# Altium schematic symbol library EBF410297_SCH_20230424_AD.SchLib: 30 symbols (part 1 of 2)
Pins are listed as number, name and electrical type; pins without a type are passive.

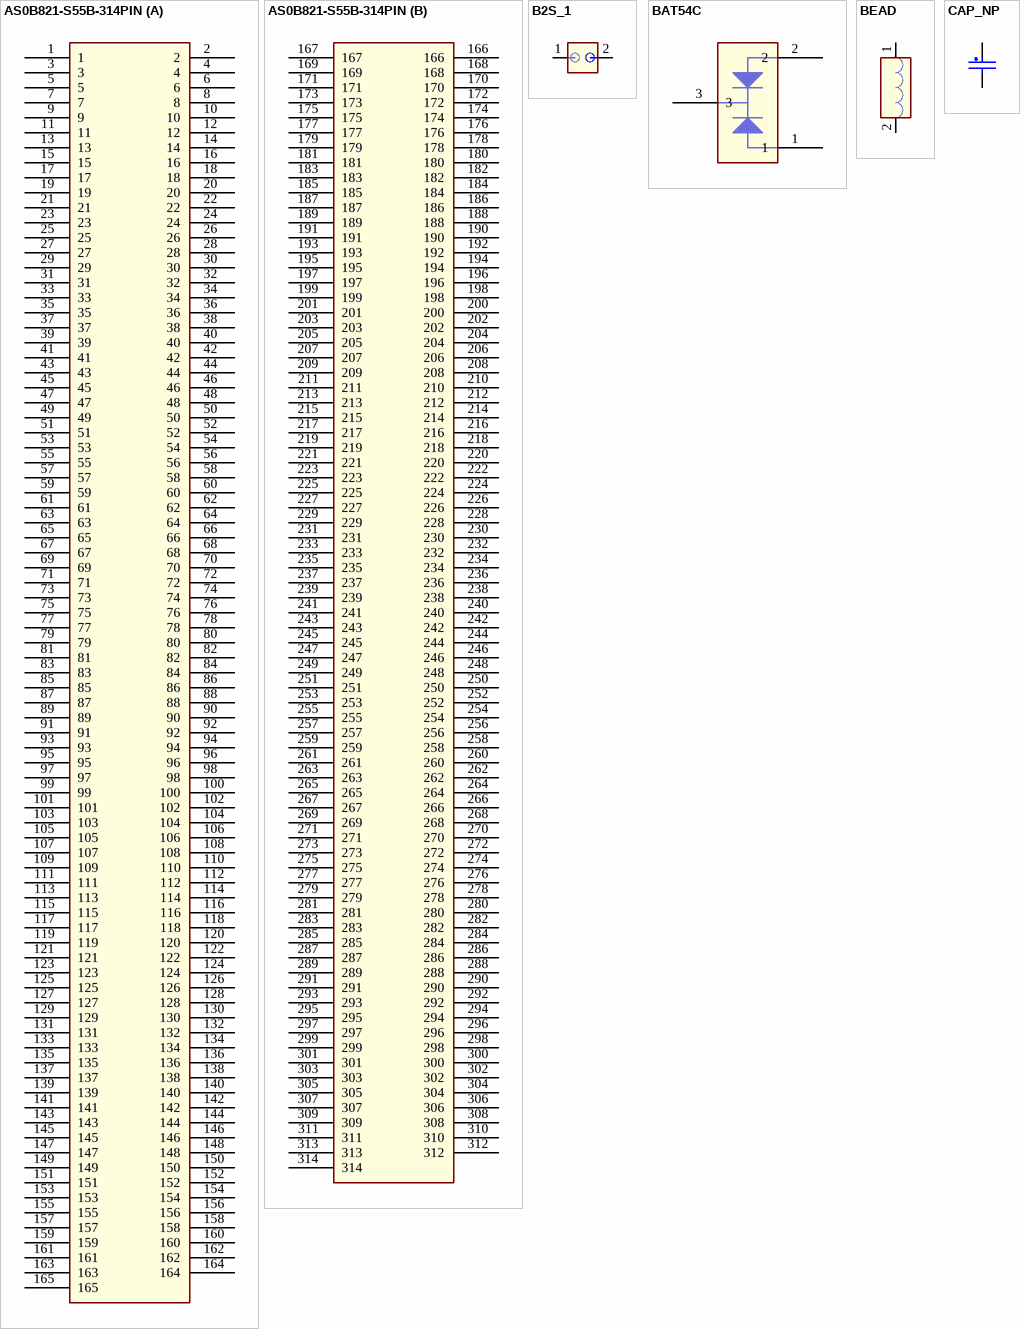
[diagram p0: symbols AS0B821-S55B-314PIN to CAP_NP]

## AS0B821-S55B-314PIN
designator J?
footprint AS0B821-S78B-314PIN
part A pins: 1, 2, 3, 4, 5, 6, 7, 8, 9, 10, 11, 12, 13, 14, 15, 16, 17, 18, 19, 20, 21, 22, 23, 24, 25, 26, 27, 28, 29, 30, 31, 32, 33, 34, 35, 36, 37, 38, 39, 40, 41, 42, 43, 44, 45, 46, 47, 48, 49, 50, 51, 52, 53, 54, 55, 56, 57, 58, 59, 60, 61, 62, 63, 64, 65, 66, 67, 68, 69, 70, 71, 72, 73, 74, 75, 76, 77, 78, 79, 80, 81, 82, 83, 84, 85, 86, 87, 88, 89, 90, 91, 92, 93, 94, 95, 96, 97, 98, 99, 100, 101, 102, 103, 104, 105, 106, 107, 108, 109, 110, 111, 112, 113, 114, 115, 116, 117, 118, 119, 120, 121, 122, 123, 124, 125, 126, 127, 128, 129, 130, 131, 132, 133, 134, 135, 136, 137, 138, 139, 140, 141, 142, 143, 144, 145, 146, 147, 148, 149, 150, 151, 152, 153, 154, 155, 156, 157, 158, 159, 160, 161, 162, 163, 164, 165
part B pins: 166, 167, 168, 169, 170, 171, 172, 173, 174, 175, 176, 177, 178, 179, 180, 181, 182, 183, 184, 185, 186, 187, 188, 189, 190, 191, 192, 193, 194, 195, 196, 197, 198, 199, 200, 201, 202, 203, 204, 205, 206, 207, 208, 209, 210, 211, 212, 213, 214, 215, 216, 217, 218, 219, 220, 221, 222, 223, 224, 225, 226, 227, 228, 229, 230, 231, 232, 233, 234, 235, 236, 237, 238, 239, 240, 241, 242, 243, 244, 245, 246, 247, 248, 249, 250, 251, 252, 253, 254, 255, 256, 257, 258, 259, 260, 261, 262, 263, 264, 265, 266, 267, 268, 269, 270, 271, 272, 273, 274, 275, 276, 277, 278, 279, 280, 281, 282, 283, 284, 285, 286, 287, 288, 289, 290, 291, 292, 293, 294, 295, 296, 297, 298, 299, 300, 301, 302, 303, 304, 305, 306, 307, 308, 309, 310, 311, 312, 313, 314

## B2S_1
designator J?
pins: 1, 2

## BAT54C
designator D?
footprint SOT23
pins: 1, 2, 3

## BEAD
designator L?
CLASS: DISCRETE
pins: 1, 2

## CAP_NP
designator C?
CLASS: DISCRETE
pins: 1, 2

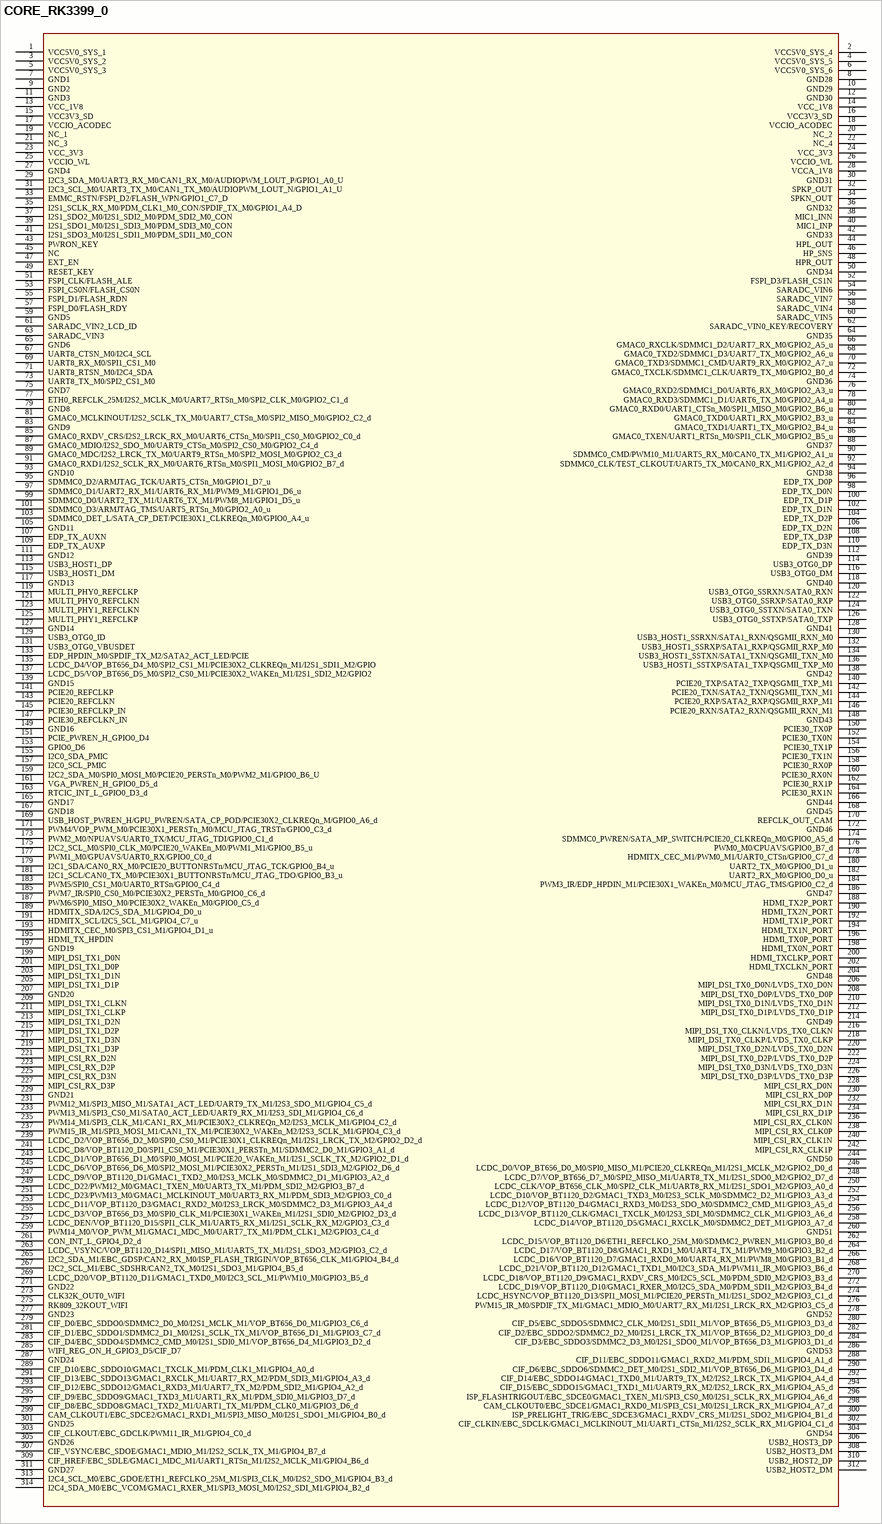
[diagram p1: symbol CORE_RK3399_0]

## CORE_RK3399_0
designator U?
pins: 1 VCC5V0_SYS_1, 2 VCC5V0_SYS_4, 3 VCC5V0_SYS_2, 4 VCC5V0_SYS_5, 5 VCC5V0_SYS_3, 6 VCC5V0_SYS_6, 7 GND1, 8 GND28, 9 GND2, 10 GND29, 11 GND3, 12 GND30, 13 VCC_1V8, 14 VCC_1V8, 15 VCC3V3_SD, 16 VCC3V3_SD, 17 VCCIO_ACODEC, 18 VCCIO_ACODEC, 19 NC_1, 20 NC_2, 21 NC_3, 22 NC_4, 23 VCC_3V3, 24 VCC_3V3, 25 VCCIO_WL, 26 VCCIO_WL, 27 GND4, 28 VCCA_1V8, 29 I2C3_SDA_M0/UART3_RX_M0/CAN1_RX_M0/AUDIOPWM_LOUT_P/GPIO1_A0_U, 30 GND31, 31 I2C3_SCL_M0/UART3_TX_M0/CAN1_TX_M0/AUDIOPWM_LOUT_N/GPIO1_A1_U, 32 SPKP_OUT, 33 EMMC_RSTN/FSPI_D2/FLASH_WPN/GPIO1_C7_D, 34 SPKN_OUT, 35 I2S1_SCLK_RX_M0/PDM_CLK1_M0_CON/SPDIF_TX_M0/GPIO1_A4_D, 36 GND32, 37 I2S1_SDO2_M0/I2S1_SDI2_M0/PDM_SDI2_M0_CON, 38 MIC1_INN, 39 I2S1_SDO1_M0/I2S1_SDI3_M0/PDM_SDI3_M0_CON, 40 MIC1_INP, 41 I2S1_SDO3_M0/I2S1_SDI1_M0/PDM_SDI1_M0_CON, 42 GND33, 43 PWRON_KEY, 44 HPL_OUT, 45 NC, 46 HP_SNS, 47 EXT_EN, 48 HPR_OUT, 49 RESET_KEY, 50 GND34, 51 FSPI_CLK/FLASH_ALE, 52 FSPI_D3/FLASH_CS1N, 53 FSPI_CS0N/FLASH_CS0N, 54 SARADC_VIN6, 55 FSPI_D1/FLASH_RDN, 56 SARADC_VIN7, 57 FSPI_D0/FLASH_RDY, 58 SARADC_VIN4, 59 GND5, 60 SARADC_VIN5, 61 SARADC_VIN2_LCD_ID, 62 SARADC_VIN0_KEY/RECOVERY, 63 SARADC_VIN3, 64 GND35, 65 GND6, 66 GMAC0_RXCLK/SDMMC1_D2/UART7_RX_M0/GPIO2_A5_u, 67 UART8_CTSN_M0/I2C4_SCL, 68 GMAC0_TXD2/SDMMC1_D3/UART7_TX_M0/GPIO2_A6_u, 69 UART8_RX_M0/SPI1_CS1_M0, 70 GMAC0_TXD3/SDMMC1_CMD/UART9_RX_M0/GPIO2_A7_u, 71 UART8_RTSN_M0/I2C4_SDA, 72 GMAC0_TXCLK/SDMMC1_CLK/UART9_TX_M0/GPIO2_B0_d, 73 UART8_TX_M0/SPI2_CS1_M0, 74 GND36, 75 GND7, 76 GMAC0_RXD2/SDMMC1_D0/UART6_RX_M0/GPIO2_A3_u, 77 ETH0_REFCLK_25M/I2S2_MCLK_M0/UART7_RTSn_M0/SPI2_CLK_M0/GPIO2_C1_d, 78 GMAC0_RXD3/SDMMC1_D1/UART6_TX_M0/GPIO2_A4_u, 79 GND8, 80 GMAC0_RXD0/UART1_CTSn_M0/SPI1_MISO_M0/GPIO2_B6_u, 81 GMAC0_MCLKINOUT/I2S2_SCLK_TX_M0/UART7_CTSn_M0/SPI2_MISO_M0/GPIO2_C2_d, 82 GMAC0_TXD0/UART1_RX_M0/GPIO2_B3_u, 83 GND9, 84 GMAC0_TXD1/UART1_TX_M0/GPIO2_B4_u, 85 GMAC0_RXDV_CRS/I2S2_LRCK_RX_M0/UART6_CTSn_M0/SPI1_CS0_M0/GPIO2_C0_d, 86 GMAC0_TXEN/UART1_RTSn_M0/SPI1_CLK_M0/GPIO2_B5_u, 87 GMAC0_MDIO/I2S2_SDO_M0/UART9_CTSn_M0/SPI2_CS0_M0/GPIO2_C4_d, 88 GND37, 89 GMAC0_MDC/I2S2_LRCK_TX_M0/UART9_RTSn_M0/SPI2_MOSI_M0/GPIO2_C3_d, 90 SDMMC0_CMD/PWM10_M1/UART5_RX_M0/CAN0_TX_M1/GPIO2_A1_u, 91 GMAC0_RXD1/I2S2_SCLK_RX_M0/UART6_RTSn_M0/SPI1_MOSI_M0/GPIO2_B7_d, 92 SDMMC0_CLK/TEST_CLKOUT/UART5_TX_M0/CAN0_RX_M1/GPIO2_A2_d, 93 GND10, 94 GND38, 95 SDMMC0_D2/ARMJTAG_TCK/UART5_CTSn_M0/GPIO1_D7_u, 96 EDP_TX_D0P, 97 SDMMC0_D1/UART2_RX_M1/UART6_RX_M1/PWM9_M1/GPIO1_D6_u, 98 EDP_TX_D0N, 99 SDMMC0_D0/UART2_TX_M1/UART6_TX_M1/PWM8_M1/GPIO1_D5_u, 100 EDP_TX_D1P, 101 SDMMC0_D3/ARMJTAG_TMS/UART5_RTSn_M0/GPIO2_A0_u, 102 EDP_TX_D1N, 103 SDMMC0_DET_L/SATA_CP_DET/PCIE30X1_CLKREQn_M0/GPIO0_A4_u, 104 EDP_TX_D2P, 105 GND11, 106 EDP_TX_D2N, 107 EDP_TX_AUXN, 108 EDP_TX_D3P, 109 EDP_TX_AUXP, 110 EDP_TX_D3N, 111 GND12, 112 GND39, 113 USB3_HOST1_DP, 114 USB3_OTG0_DP, 115 USB3_HOST1_DM, 116 USB3_OTG0_DM, 117 GND13, 118 GND40, 119 MULTI_PHY0_REFCLKP, 120 USB3_OTG0_SSRXN/SATA0_RXN, 121 MULTI_PHY0_REFCLKN, 122 USB3_OTG0_SSRXP/SATA0_RXP, 123 MULTI_PHY1_REFCLKN, 124 USB3_OTG0_SSTXN/SATA0_TXN, 125 MULTI_PHY1_REFCLKP, 126 USB3_OTG0_SSTXP/SATA0_TXP, 127 GND14, 128 GND41, 129 USB3_OTG0_ID, 130 USB3_HOST1_SSRXN/SATA1_RXN/QSGMII_RXN_M0, 131 USB3_OTG0_VBUSDET, 132 USB3_HOST1_SSRXP/SATA1_RXP/QSGMII_RXP_M0, 133 EDP_HPDIN_M0/SPDIF_TX_M2/SATA2_ACT_LED/PCIE, 134 USB3_HOST1_SSTXN/SATA1_TXN/QSGMII_TXN_M0, 135 LCDC_D4/VOP_BT656_D4_M0/SPI2_CS1_M1/PCIE30X2_CLKREQn_M1/I2S1_SDI1_M2/GPIO, 136 USB3_HOST1_SSTXP/SATA1_TXP/QSGMII_TXP_M0, 137 LCDC_D5/VOP_BT656_D5_M0/SPI2_CS0_M1/PCIE30X2_WAKEn_M1/I2S1_SDI2_M2/GPIO2, 138 GND42, 139 GND15, 140 PCIE20_TXP/SATA2_TXP/QSGMII_TXP_M1, 141 PCIE20_REFCLKP, 142 PCIE20_TXN/SATA2_TXN/QSGMII_TXN_M1, 143 PCIE20_REFCLKN, 144 PCIE20_RXP/SATA2_RXP/QSGMII_RXP_M1, 145 PCIE30_REFCLKP_IN, 146 PCIE20_RXN/SATA2_RXN/QSGMII_RXN_M1, 147 PCIE30_REFCLKN_IN, 148 GND43, 149 GND16, 150 PCIE30_TX0P, 151 PCIE_PWREN_H_GPIO0_D4, 152 PCIE30_TX0N, 153 GPIO0_D6, 154 PCIE30_TX1P, 155 I2C0_SDA_PMIC, 156 PCIE30_TX1N, 157 I2C0_SCL_PMIC, 158 PCIE30_RX0P, 159 I2C2_SDA_M0/SPI0_MOSI_M0/PCIE20_PERSTn_M0/PWM2_M1/GPIO0_B6_U, 160 PCIE30_RX0N, 161 VGA_PWREN_H_GPIO0_D5_d, 162 PCIE30_RX1P, 163 RTCIC_INT_L_GPIO0_D3_d, 164 PCIE30_RX1N, 165 GND17, 166 GND44, 167 GND18, 168 GND45, 169 USB_HOST_PWREN_H/GPU_PWREN/SATA_CP_POD/PCIE30X2_CLKREQn_M/GPIO0_A6_d, 170 REFCLK_OUT_CAM, 171 PWM4/VOP_PWM_M0/PCIE30X1_PERSTn_M0/MCU_JTAG_TRSTn/GPIO0_C3_d, 172 GND46, 173 PWM2_M0/NPUAVS/UART0_TX/MCU_JTAG_TDI/GPIO0_C1_d, 174 SDMMC0_PWREN/SATA_MP_SWITCH/PCIE20_CLKREQn_M0/GPIO0_A5_d, 175 I2C2_SCL_M0/SPI0_CLK_M0/PCIE20_WAKEn_M0/PWM1_M1/GPIO0_B5_u, 176 PWM0_M0/CPUAVS/GPIO0_B7_d, 177 PWM1_M0/GPUAVS/UART0_RX/GPIO0_C0_d, 178 HDMITX_CEC_M1/PWM0_M1/UART0_CTSn/GPIO0_C7_d, 179 I2C1_SDA/CAN0_RX_M0/PCIE20_BUTTONRSTn/MCU_JTAG_TCK/GPIO0_B4_u, 180 UART2_TX_M0/GPIO0_D1_u, 181 I2C1_SCL/CAN0_TX_M0/PCIE30X1_BUTTONRSTn/MCU_JTAG_TDO/GPIO0_B3_u, 182 UART2_RX_M0/GPIO0_D0_u, 183 PWM5/SPI0_CS1_M0/UART0_RTSn/GPIO0_C4_d, 184 PWM3_IR/EDP_HPDIN_M1/PCIE30X1_WAKEn_M0/MCU_JTAG_TMS/GPIO0_C2_d, 185 PWM7_IR/SPI0_CS0_M0/PCIE30X2_PERSTn_M0/GPIO0_C6_d, 186 GND47, 187 PWM6/SPI0_MISO_M0/PCIE30X2_WAKEn_M0/GPIO0_C5_d, 188 HDMI_TX2P_PORT, 189 HDMITX_SDA/I2C5_SDA_M1/GPIO4_D0_u, 190 HDMI_TX2N_PORT, 191 HDMITX_SCL/I2C5_SCL_M1/GPIO4_C7_u, 192 HDMI_TX1P_PORT, 193 HDMITX_CEC_M0/SPI3_CS1_M1/GPIO4_D1_u, 194 HDMI_TX1N_PORT, 195 HDMI_TX_HPDIN, 196 HDMI_TX0P_PORT, 197 GND19, 198 HDMI_TX0N_PORT, 199 MIPI_DSI_TX1_D0N, 200 HDMI_TXCLKP_PORT, 201 MIPI_DSI_TX1_D0P, 202 HDMI_TXCLKN_PORT, 203 MIPI_DSI_TX1_D1N, 204 GND48, 205 MIPI_DSI_TX1_D1P, 206 MIPI_DSI_TX0_D0N/LVDS_TX0_D0N, 207 GND20, 208 MIPI_DSI_TX0_D0P/LVDS_TX0_D0P, 209 MIPI_DSI_TX1_CLKN, 210 MIPI_DSI_TX0_D1N/LVDS_TX0_D1N, 211 MIPI_DSI_TX1_CLKP, 212 MIPI_DSI_TX0_D1P/LVDS_TX0_D1P, 213 MIPI_DSI_TX1_D2N, 214 GND49, 215 MIPI_DSI_TX1_D2P, 216 MIPI_DSI_TX0_CLKN/LVDS_TX0_CLKN, 217 MIPI_DSI_TX1_D3N, 218 MIPI_DSI_TX0_CLKP/LVDS_TX0_CLKP, 219 MIPI_DSI_TX1_D3P, 220 MIPI_DSI_TX0_D2N/LVDS_TX0_D2N, 221 MIPI_CSI_RX_D2N, 222 MIPI_DSI_TX0_D2P/LVDS_TX0_D2P, 223 MIPI_CSI_RX_D2P, 224 MIPI_DSI_TX0_D3N/LVDS_TX0_D3N, 225 MIPI_CSI_RX_D3N, 226 MIPI_DSI_TX0_D3P/LVDS_TX0_D3P, 227 MIPI_CSI_RX_D3P, 228 MIPI_CSI_RX_D0N, 229 GND21, 230 MIPI_CSI_RX_D0P, 231 PWM12_M1/SPI3_MISO_M1/SATA1_ACT_LED/UART9_TX_M1/I2S3_SDO_M1/GPIO4_C5_d, 232 MIPI_CSI_RX_D1N, 233 PWM13_M1/SPI3_CS0_M1/SATA0_ACT_LED/UART9_RX_M1/I2S3_SDI_M1/GPIO4_C6_d, 234 MIPI_CSI_RX_D1P, 235 PWM14_M1/SPI3_CLK_M1/CAN1_RX_M1/PCIE30X2_CLKREQn_M2/I2S3_MCLK_M1/GPIO4_C2_d, 236 MIPI_CSI_RX_CLK0N, 237 PWM15_IR_M1/SPI3_MOSI_M1/CAN1_TX_M1/PCIE30X2_WAKEn_M2/I2S3_SCLK_M1/GPIO4_C3_d, 238 MIPI_CSI_RX_CLK0P, 239 LCDC_D2/VOP_BT656_D2_M0/SPI0_CS0_M1/PCIE30X1_CLKREQn_M1/I2S1_LRCK_TX_M2/GPIO2_D2_d, 240 MIPI_CSI_RX_CLK1N, 241 LCDC_D8/VOP_BT1120_D0/SPI1_CS0_M1/PCIE30X1_PERSTn_M1/SDMMC2_D0_M1/GPIO3_A1_d, 242 MIPI_CSI_RX_CLK1P, 243 LCDC_D1/VOP_BT656_D1_M0/SPI0_MOSI_M1/PCIE20_WAKEn_M1/I2S1_SCLK_TX_M2/GPIO2_D1_d, 244 GND50, 245 LCDC_D6/VOP_BT656_D6_M0/SPI2_MOSI_M1/PCIE30X2_PERSTn_M1/I2S1_SDI3_M2/GPIO2_D6_d, 246 LCDC_D0/VOP_BT656_D0_M0/SPI0_MISO_M1/PCIE20_CLKREQn_M1/I2S1_MCLK_M2/GPIO2_D0_d, 247 LCDC_D9/VOP_BT1120_D1/GMAC1_TXD2_M0/I2S3_MCLK_M0/SDMMC2_D1_M1/GPIO3_A2_d, 248 LCDC_D7/VOP_BT656_D7_M0/SPI2_MISO_M1/UART8_TX_M1/I2S1_SDO0_M2/GPIO2_D7_d, 249 LCDC_D22/PWM12_M0/GMAC1_TXEN_M0/UART3_TX_M1/PDM_SDI2_M2/GPIO3_B7_d, 250 LCDC_CLK/VOP_BT656_CLK_M0/SPI2_CLK_M1/UART8_RX_M1/I2S1_SDO1_M2/GPIO3_A0_d, 251 LCDC_D23/PWM13_M0/GMAC1_MCLKINOUT_M0/UART3_RX_M1/PDM_SDI3_M2/GPIO3_C0_d, 252 LCDC_D10/VOP_BT1120_D2/GMAC1_TXD3_M0/I2S3_SCLK_M0/SDMMC2_D2_M1/GPIO3_A3_d, 253 LCDC_D11/VOP_BT1120_D3/GMAC1_RXD2_M0/I2S3_LRCK_M0/SDMMC2_D3_M1/GPIO3_A4_d, 254 LCDC_D12/VOP_BT1120_D4/GMAC1_RXD3_M0/I2S3_SDO_M0/SDMMC2_CMD_M1/GPIO3_A5_d, 255 LCDC_D3/VOP_BT656_D3_M0/SPI0_CLK_M1/PCIE30X1_WAKEn_M1/I2S1_SDI0_M2/GPIO2_D3_d, 256 LCDC_D13/VOP_BT1120_CLK/GMAC1_TXCLK_M0/I2S3_SDI_M0/SDMMC2_CLK_M1/GPIO3_A6_d, 257 LCDC_DEN/VOP_BT1120_D15/SPI1_CLK_M1/UART5_RX_M1/I2S1_SCLK_RX_M2/GPIO3_C3_d, 258 LCDC_D14/VOP_BT1120_D5/GMAC1_RXCLK_M0/SDMMC2_DET_M1/GPIO3_A7_d, 259 PWM14_M0/VOP_PWM_M1/GMAC1_MDC_M0/UART7_TX_M1/PDM_CLK1_M2/GPIO3_C4_d, 260 GND51, 261 CON_INT_L_GPIO4_D2_d, 262 LCDC_D15/VOP_BT1120_D6/ETH1_REFCLKO_25M_M0/SDMMC2_PWREN_M1/GPIO3_B0_d, 263 LCDC_VSYNC/VOP_BT1120_D14/SPI1_MISO_M1/UART5_TX_M1/I2S1_SDO3_M2/GPIO3_C2_d, 264 LCDC_D17/VOP_BT1120_D8/GMAC1_RXD1_M0/UART4_TX_M1/PWM9_M0/GPIO3_B2_d, 265 I2C2_SDA_M1/EBC_GDSP/CAN2_RX_M0/ISP_FLASH_TRIGIN/VOP_BT656_CLK_M1/GPIO4_B4_d, 266 LCDC_D16/VOP_BT1120_D7/GMAC1_RXD0_M0/UART4_RX_M1/PWM8_M0/GPIO3_B1_d, 267 I2C2_SCL_M1/EBC_SDSHR/CAN2_TX_M0/I2S1_SDO3_M1/GPIO4_B5_d, 268 LCDC_D21/VOP_BT1120_D12/GMAC1_TXD1_M0/I2C3_SDA_M1/PWM11_IR_M0/GPIO3_B6_d, 269 LCDC_D20/VOP_BT1120_D11/GMAC1_TXD0_M0/I2C3_SCL_M1/PWM10_M0/GPIO3_B5_d, 270 LCDC_D18/VOP_BT1120_D9/GMAC1_RXDV_CRS_M0/I2C5_SCL_M0/PDM_SDI0_M2/GPIO3_B3_d, 271 GND22, 272 LCDC_D19/VOP_BT1120_D10/GMAC1_RXER_M0/I2C5_SDA_M0/PDM_SDI1_M2/GPIO3_B4_d, 273 CLK32K_OUT0_WIFI, 274 LCDC_HSYNC/VOP_BT1120_D13/SPI1_MOSI_M1/PCIE20_PERSTn_M1/I2S1_SDO2_M2/GPIO3_C1_d, 275 RK809_32KOUT_WIFI, 276 PWM15_IR_M0/SPDIF_TX_M1/GMAC1_MDIO_M0/UART7_RX_M1/I2S1_LRCK_RX_M2/GPIO3_C5_d, 277 GND23, 278 GND52, 279 CIF_D0/EBC_SDDO0/SDMMC2_D0_M0/I2S1_MCLK_M1/VOP_BT656_D0_M1/GPIO3_C6_d, 280 CIF_D5/EBC_SDDO5/SDMMC2_CLK_M0/I2S1_SDI1_M1/VOP_BT656_D5_M1/GPIO3_D3_d, 281 CIF_D1/EBC_SDDO1/SDMMC2_D1_M0/I2S1_SCLK_TX_M1/VOP_BT656_D1_M1/GPIO3_C7_d, 282 CIF_D2/EBC_SDDO2/SDMMC2_D2_M0/I2S1_LRCK_TX_M1/VOP_BT656_D2_M1/GPIO3_D0_d, 283 CIF_D4/EBC_SDDO4/SDMMC2_CMD_M0/I2S1_SDI0_M1/VOP_BT656_D4_M1/GPIO3_D2_d, 284 CIF_D3/EBC_SDDO3/SDMMC2_D3_M0/I2S1_SDO0_M1/VOP_BT656_D3_M1/GPIO3_D1_d, 285 WIFI_REG_ON_H_GPIO3_D5/CIF_D7, 286 GND53, 287 GND24, 288 CIF_D11/EBC_SDDO11/GMAC1_RXD2_M1/PDM_SDI1_M1/GPIO4_A1_d, 289 CIF_D10/EBC_SDDO10/GMAC1_TXCLK_M1/PDM_CLK1_M1/GPIO4_A0_d, 290 CIF_D6/EBC_SDDO6/SDMMC2_DET_M0/I2S1_SDI2_M1/VOP_BT656_D6_M1/GPIO3_D4_d, 291 CIF_D13/EBC_SDDO13/GMAC1_RXCLK_M1/UART7_RX_M2/PDM_SDI3_M1/GPIO4_A3_d, 292 CIF_D14/EBC_SDDO14/GMAC1_TXD0_M1/UART9_TX_M2/I2S2_LRCK_TX_M1/GPIO4_A4_d, 293 CIF_D12/EBC_SDDO12/GMAC1_RXD3_M1/UART7_TX_M2/PDM_SDI2_M1/GPIO4_A2_d, 294 CIF_D15/EBC_SDDO15/GMAC1_TXD1_M1/UART9_RX_M2/I2S2_LRCK_RX_M1/GPIO4_A5_d, 295 CIF_D9/EBC_SDDO9/GMAC1_TXD3_M1/UART1_RX_M1/PDM_SDI0_M1/GPIO3_D7_d, 296 ISP_FLASHTRIGOUT/EBC_SDCE0/GMAC1_TXEN_M1/SPI3_CS0_M0/I2S1_SCLK_RX_M1/GPIO4_A6_d, 297 CIF_D8/EBC_SDDO8/GMAC1_TXD2_M1/UART1_TX_M1/PDM_CLK0_M1/GPIO3_D6_d, 298 CAM_CLKOUT0/EBC_SDCE1/GMAC1_RXD0_M1/SPI3_CS1_M0/I2S1_LRCK_RX_M1/GPIO4_A7_d, 299 CAM_CLKOUT1/EBC_SDCE2/GMAC1_RXD1_M1/SPI3_MISO_M0/I2S1_SDO1_M1/GPIO4_B0_d, 300 ISP_PRELIGHT_TRIG/EBC_SDCE3/GMAC1_RXDV_CRS_M1/I2S1_SDO2_M1/GPIO4_B1_d, 301 GND25, 302 CIF_CLKIN/EBC_SDCLK/GMAC1_MCLKINOUT_M1/UART1_CTSn_M1/I2S2_SCLK_RX_M1/GPIO4_C1_d, 303 CIF_CLKOUT/EBC_GDCLK/PWM11_IR_M1/GPIO4_C0_d, 304 GND54, 305 GND26, 306 USB2_HOST3_DP, 307 CIF_VSYNC/EBC_SDOE/GMAC1_MDIO_M1/I2S2_SCLK_TX_M1/GPIO4_B7_d, 308 USB2_HOST3_DM, 309 CIF_HREF/EBC_SDLE/GMAC1_MDC_M1/UART1_RTSn_M1/I2S2_MCLK_M1/GPIO4_B6_d, 310 USB2_HOST2_DP, 311 GND27, 312 USB2_HOST2_DM, 313 I2C4_SCL_M0/EBC_GDOE/ETH1_REFCLKO_25M_M1/SPI3_CLK_M0/I2S2_SDO_M1/GPIO4_B3_d, 314 I2C4_SDA_M0/EBC_VCOM/GMAC1_RXER_M1/SPI3_MOSI_M0/I2S2_SDI_M1/GPIO4_B2_d

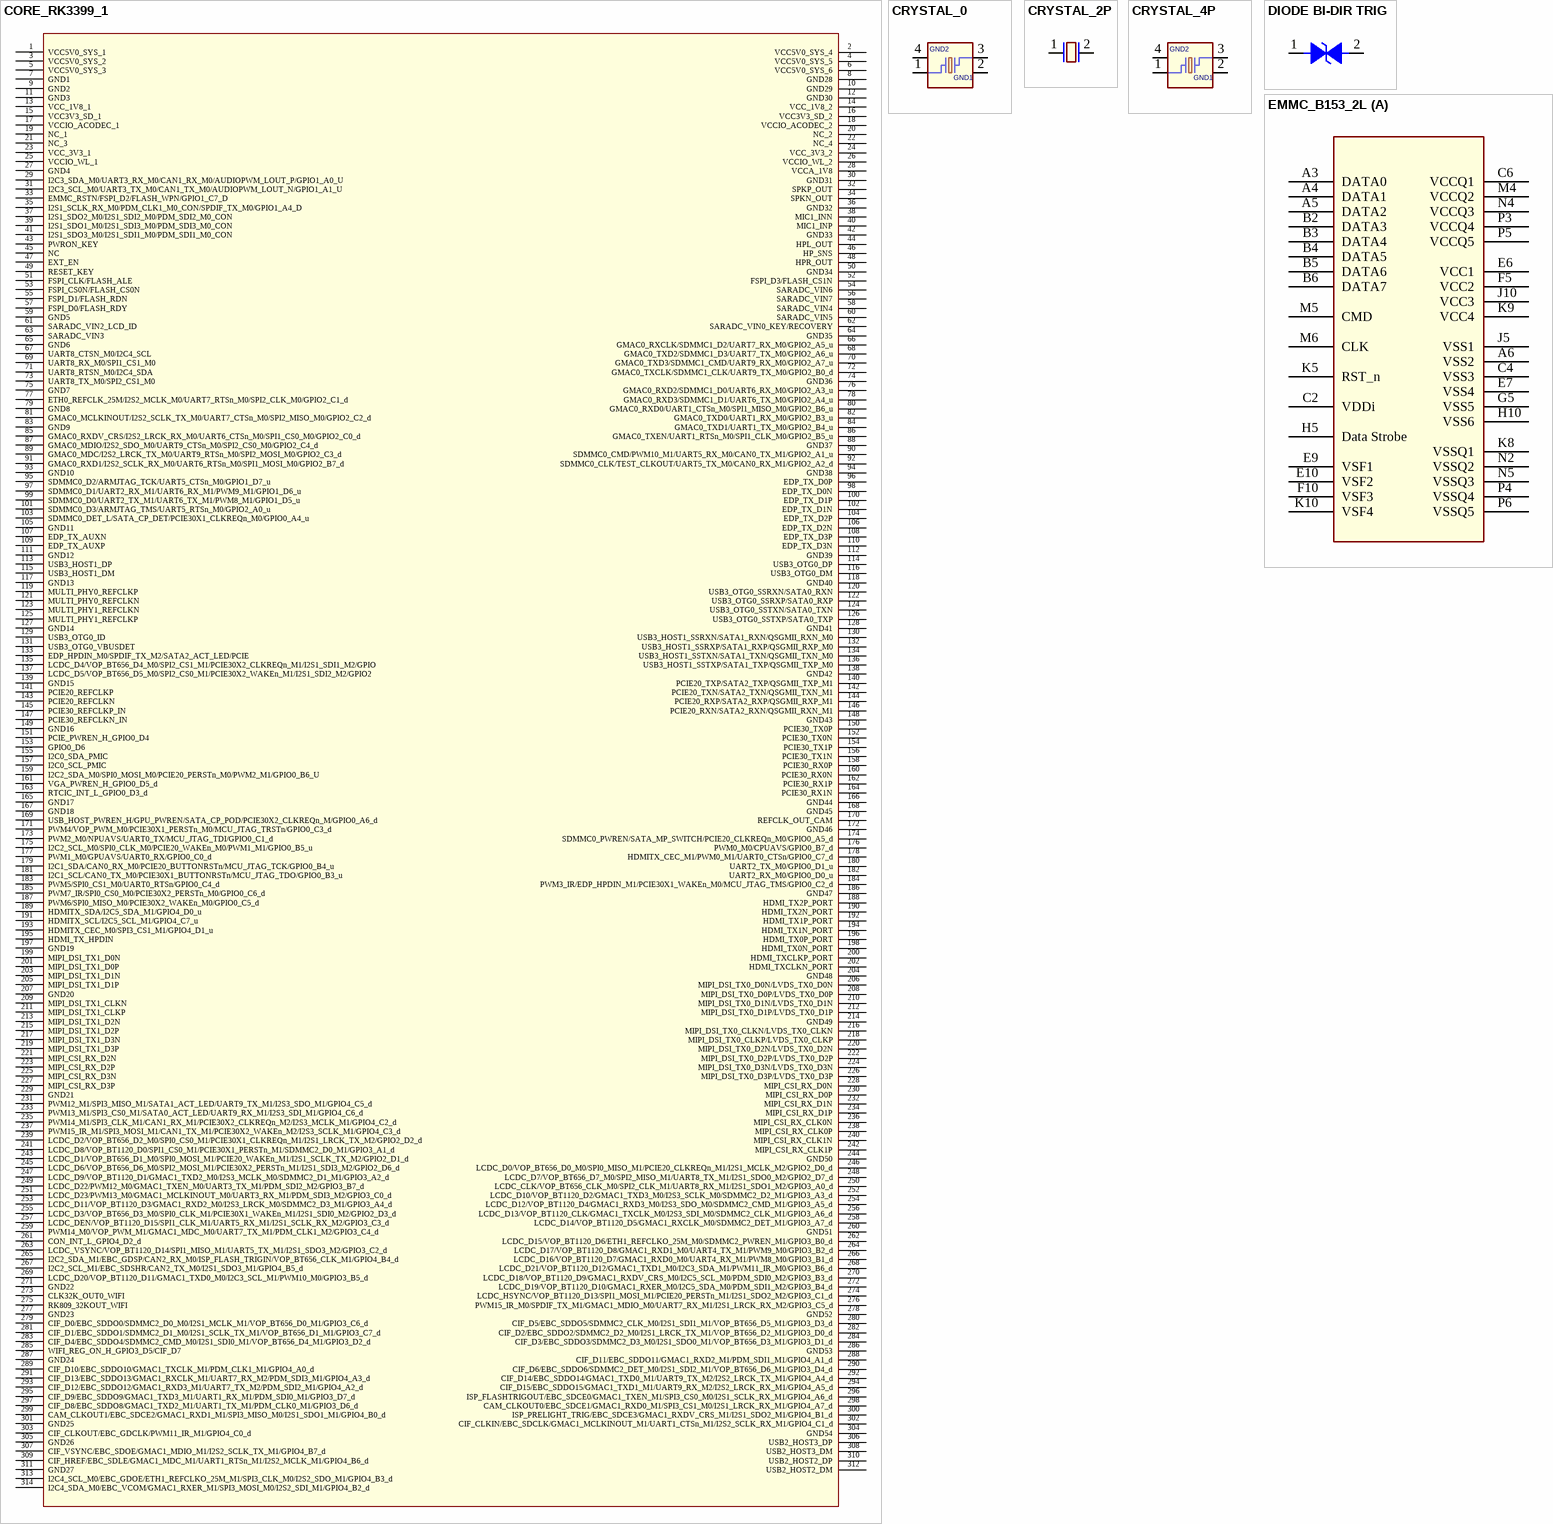
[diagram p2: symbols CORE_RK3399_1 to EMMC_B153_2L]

## CORE_RK3399_1
designator U?
pins: 1 VCC5V0_SYS_1, 2 VCC5V0_SYS_4, 3 VCC5V0_SYS_2, 4 VCC5V0_SYS_5, 5 VCC5V0_SYS_3, 6 VCC5V0_SYS_6, 7 GND1, 8 GND28, 9 GND2, 10 GND29, 11 GND3, 12 GND30, 13 VCC_1V8_1, 14 VCC_1V8_2, 15 VCC3V3_SD_1, 16 VCC3V3_SD_2, 17 VCCIO_ACODEC_1, 18 VCCIO_ACODEC_2, 19 NC_1, 20 NC_2, 21 NC_3, 22 NC_4, 23 VCC_3V3_1, 24 VCC_3V3_2, 25 VCCIO_WL_1, 26 VCCIO_WL_2, 27 GND4, 28 VCCA_1V8, 29 I2C3_SDA_M0/UART3_RX_M0/CAN1_RX_M0/AUDIOPWM_LOUT_P/GPIO1_A0_U, 30 GND31, 31 I2C3_SCL_M0/UART3_TX_M0/CAN1_TX_M0/AUDIOPWM_LOUT_N/GPIO1_A1_U, 32 SPKP_OUT, 33 EMMC_RSTN/FSPI_D2/FLASH_WPN/GPIO1_C7_D, 34 SPKN_OUT, 35 I2S1_SCLK_RX_M0/PDM_CLK1_M0_CON/SPDIF_TX_M0/GPIO1_A4_D, 36 GND32, 37 I2S1_SDO2_M0/I2S1_SDI2_M0/PDM_SDI2_M0_CON, 38 MIC1_INN, 39 I2S1_SDO1_M0/I2S1_SDI3_M0/PDM_SDI3_M0_CON, 40 MIC1_INP, 41 I2S1_SDO3_M0/I2S1_SDI1_M0/PDM_SDI1_M0_CON, 42 GND33, 43 PWRON_KEY, 44 HPL_OUT, 45 NC, 46 HP_SNS, 47 EXT_EN, 48 HPR_OUT, 49 RESET_KEY, 50 GND34, 51 FSPI_CLK/FLASH_ALE, 52 FSPI_D3/FLASH_CS1N, 53 FSPI_CS0N/FLASH_CS0N, 54 SARADC_VIN6, 55 FSPI_D1/FLASH_RDN, 56 SARADC_VIN7, 57 FSPI_D0/FLASH_RDY, 58 SARADC_VIN4, 59 GND5, 60 SARADC_VIN5, 61 SARADC_VIN2_LCD_ID, 62 SARADC_VIN0_KEY/RECOVERY, 63 SARADC_VIN3, 64 GND35, 65 GND6, 66 GMAC0_RXCLK/SDMMC1_D2/UART7_RX_M0/GPIO2_A5_u, 67 UART8_CTSN_M0/I2C4_SCL, 68 GMAC0_TXD2/SDMMC1_D3/UART7_TX_M0/GPIO2_A6_u, 69 UART8_RX_M0/SPI1_CS1_M0, 70 GMAC0_TXD3/SDMMC1_CMD/UART9_RX_M0/GPIO2_A7_u, 71 UART8_RTSN_M0/I2C4_SDA, 72 GMAC0_TXCLK/SDMMC1_CLK/UART9_TX_M0/GPIO2_B0_d, 73 UART8_TX_M0/SPI2_CS1_M0, 74 GND36, 75 GND7, 76 GMAC0_RXD2/SDMMC1_D0/UART6_RX_M0/GPIO2_A3_u, 77 ETH0_REFCLK_25M/I2S2_MCLK_M0/UART7_RTSn_M0/SPI2_CLK_M0/GPIO2_C1_d, 78 GMAC0_RXD3/SDMMC1_D1/UART6_TX_M0/GPIO2_A4_u, 79 GND8, 80 GMAC0_RXD0/UART1_CTSn_M0/SPI1_MISO_M0/GPIO2_B6_u, 81 GMAC0_MCLKINOUT/I2S2_SCLK_TX_M0/UART7_CTSn_M0/SPI2_MISO_M0/GPIO2_C2_d, 82 GMAC0_TXD0/UART1_RX_M0/GPIO2_B3_u, 83 GND9, 84 GMAC0_TXD1/UART1_TX_M0/GPIO2_B4_u, 85 GMAC0_RXDV_CRS/I2S2_LRCK_RX_M0/UART6_CTSn_M0/SPI1_CS0_M0/GPIO2_C0_d, 86 GMAC0_TXEN/UART1_RTSn_M0/SPI1_CLK_M0/GPIO2_B5_u, 87 GMAC0_MDIO/I2S2_SDO_M0/UART9_CTSn_M0/SPI2_CS0_M0/GPIO2_C4_d, 88 GND37, 89 GMAC0_MDC/I2S2_LRCK_TX_M0/UART9_RTSn_M0/SPI2_MOSI_M0/GPIO2_C3_d, 90 SDMMC0_CMD/PWM10_M1/UART5_RX_M0/CAN0_TX_M1/GPIO2_A1_u, 91 GMAC0_RXD1/I2S2_SCLK_RX_M0/UART6_RTSn_M0/SPI1_MOSI_M0/GPIO2_B7_d, 92 SDMMC0_CLK/TEST_CLKOUT/UART5_TX_M0/CAN0_RX_M1/GPIO2_A2_d, 93 GND10, 94 GND38, 95 SDMMC0_D2/ARMJTAG_TCK/UART5_CTSn_M0/GPIO1_D7_u, 96 EDP_TX_D0P, 97 SDMMC0_D1/UART2_RX_M1/UART6_RX_M1/PWM9_M1/GPIO1_D6_u, 98 EDP_TX_D0N, 99 SDMMC0_D0/UART2_TX_M1/UART6_TX_M1/PWM8_M1/GPIO1_D5_u, 100 EDP_TX_D1P, 101 SDMMC0_D3/ARMJTAG_TMS/UART5_RTSn_M0/GPIO2_A0_u, 102 EDP_TX_D1N, 103 SDMMC0_DET_L/SATA_CP_DET/PCIE30X1_CLKREQn_M0/GPIO0_A4_u, 104 EDP_TX_D2P, 105 GND11, 106 EDP_TX_D2N, 107 EDP_TX_AUXN, 108 EDP_TX_D3P, 109 EDP_TX_AUXP, 110 EDP_TX_D3N, 111 GND12, 112 GND39, 113 USB3_HOST1_DP, 114 USB3_OTG0_DP, 115 USB3_HOST1_DM, 116 USB3_OTG0_DM, 117 GND13, 118 GND40, 119 MULTI_PHY0_REFCLKP, 120 USB3_OTG0_SSRXN/SATA0_RXN, 121 MULTI_PHY0_REFCLKN, 122 USB3_OTG0_SSRXP/SATA0_RXP, 123 MULTI_PHY1_REFCLKN, 124 USB3_OTG0_SSTXN/SATA0_TXN, 125 MULTI_PHY1_REFCLKP, 126 USB3_OTG0_SSTXP/SATA0_TXP, 127 GND14, 128 GND41, 129 USB3_OTG0_ID, 130 USB3_HOST1_SSRXN/SATA1_RXN/QSGMII_RXN_M0, 131 USB3_OTG0_VBUSDET, 132 USB3_HOST1_SSRXP/SATA1_RXP/QSGMII_RXP_M0, 133 EDP_HPDIN_M0/SPDIF_TX_M2/SATA2_ACT_LED/PCIE, 134 USB3_HOST1_SSTXN/SATA1_TXN/QSGMII_TXN_M0, 135 LCDC_D4/VOP_BT656_D4_M0/SPI2_CS1_M1/PCIE30X2_CLKREQn_M1/I2S1_SDI1_M2/GPIO, 136 USB3_HOST1_SSTXP/SATA1_TXP/QSGMII_TXP_M0, 137 LCDC_D5/VOP_BT656_D5_M0/SPI2_CS0_M1/PCIE30X2_WAKEn_M1/I2S1_SDI2_M2/GPIO2, 138 GND42, 139 GND15, 140 PCIE20_TXP/SATA2_TXP/QSGMII_TXP_M1, 141 PCIE20_REFCLKP, 142 PCIE20_TXN/SATA2_TXN/QSGMII_TXN_M1, 143 PCIE20_REFCLKN, 144 PCIE20_RXP/SATA2_RXP/QSGMII_RXP_M1, 145 PCIE30_REFCLKP_IN, 146 PCIE20_RXN/SATA2_RXN/QSGMII_RXN_M1, 147 PCIE30_REFCLKN_IN, 148 GND43, 149 GND16, 150 PCIE30_TX0P, 151 PCIE_PWREN_H_GPIO0_D4, 152 PCIE30_TX0N, 153 GPIO0_D6, 154 PCIE30_TX1P, 155 I2C0_SDA_PMIC, 156 PCIE30_TX1N, 157 I2C0_SCL_PMIC, 158 PCIE30_RX0P, 159 I2C2_SDA_M0/SPI0_MOSI_M0/PCIE20_PERSTn_M0/PWM2_M1/GPIO0_B6_U, 160 PCIE30_RX0N, 161 VGA_PWREN_H_GPIO0_D5_d, 162 PCIE30_RX1P, 163 RTCIC_INT_L_GPIO0_D3_d, 164 PCIE30_RX1N, 165 GND17, 166 GND44, 167 GND18, 168 GND45, 169 USB_HOST_PWREN_H/GPU_PWREN/SATA_CP_POD/PCIE30X2_CLKREQn_M/GPIO0_A6_d, 170 REFCLK_OUT_CAM, 171 PWM4/VOP_PWM_M0/PCIE30X1_PERSTn_M0/MCU_JTAG_TRSTn/GPIO0_C3_d, 172 GND46, 173 PWM2_M0/NPUAVS/UART0_TX/MCU_JTAG_TDI/GPIO0_C1_d, 174 SDMMC0_PWREN/SATA_MP_SWITCH/PCIE20_CLKREQn_M0/GPIO0_A5_d, 175 I2C2_SCL_M0/SPI0_CLK_M0/PCIE20_WAKEn_M0/PWM1_M1/GPIO0_B5_u, 176 PWM0_M0/CPUAVS/GPIO0_B7_d, 177 PWM1_M0/GPUAVS/UART0_RX/GPIO0_C0_d, 178 HDMITX_CEC_M1/PWM0_M1/UART0_CTSn/GPIO0_C7_d, 179 I2C1_SDA/CAN0_RX_M0/PCIE20_BUTTONRSTn/MCU_JTAG_TCK/GPIO0_B4_u, 180 UART2_TX_M0/GPIO0_D1_u, 181 I2C1_SCL/CAN0_TX_M0/PCIE30X1_BUTTONRSTn/MCU_JTAG_TDO/GPIO0_B3_u, 182 UART2_RX_M0/GPIO0_D0_u, 183 PWM5/SPI0_CS1_M0/UART0_RTSn/GPIO0_C4_d, 184 PWM3_IR/EDP_HPDIN_M1/PCIE30X1_WAKEn_M0/MCU_JTAG_TMS/GPIO0_C2_d, 185 PWM7_IR/SPI0_CS0_M0/PCIE30X2_PERSTn_M0/GPIO0_C6_d, 186 GND47, 187 PWM6/SPI0_MISO_M0/PCIE30X2_WAKEn_M0/GPIO0_C5_d, 188 HDMI_TX2P_PORT, 189 HDMITX_SDA/I2C5_SDA_M1/GPIO4_D0_u, 190 HDMI_TX2N_PORT, 191 HDMITX_SCL/I2C5_SCL_M1/GPIO4_C7_u, 192 HDMI_TX1P_PORT, 193 HDMITX_CEC_M0/SPI3_CS1_M1/GPIO4_D1_u, 194 HDMI_TX1N_PORT, 195 HDMI_TX_HPDIN, 196 HDMI_TX0P_PORT, 197 GND19, 198 HDMI_TX0N_PORT, 199 MIPI_DSI_TX1_D0N, 200 HDMI_TXCLKP_PORT, 201 MIPI_DSI_TX1_D0P, 202 HDMI_TXCLKN_PORT, 203 MIPI_DSI_TX1_D1N, 204 GND48, 205 MIPI_DSI_TX1_D1P, 206 MIPI_DSI_TX0_D0N/LVDS_TX0_D0N, 207 GND20, 208 MIPI_DSI_TX0_D0P/LVDS_TX0_D0P, 209 MIPI_DSI_TX1_CLKN, 210 MIPI_DSI_TX0_D1N/LVDS_TX0_D1N, 211 MIPI_DSI_TX1_CLKP, 212 MIPI_DSI_TX0_D1P/LVDS_TX0_D1P, 213 MIPI_DSI_TX1_D2N, 214 GND49, 215 MIPI_DSI_TX1_D2P, 216 MIPI_DSI_TX0_CLKN/LVDS_TX0_CLKN, 217 MIPI_DSI_TX1_D3N, 218 MIPI_DSI_TX0_CLKP/LVDS_TX0_CLKP, 219 MIPI_DSI_TX1_D3P, 220 MIPI_DSI_TX0_D2N/LVDS_TX0_D2N, 221 MIPI_CSI_RX_D2N, 222 MIPI_DSI_TX0_D2P/LVDS_TX0_D2P, 223 MIPI_CSI_RX_D2P, 224 MIPI_DSI_TX0_D3N/LVDS_TX0_D3N, 225 MIPI_CSI_RX_D3N, 226 MIPI_DSI_TX0_D3P/LVDS_TX0_D3P, 227 MIPI_CSI_RX_D3P, 228 MIPI_CSI_RX_D0N, 229 GND21, 230 MIPI_CSI_RX_D0P, 231 PWM12_M1/SPI3_MISO_M1/SATA1_ACT_LED/UART9_TX_M1/I2S3_SDO_M1/GPIO4_C5_d, 232 MIPI_CSI_RX_D1N, 233 PWM13_M1/SPI3_CS0_M1/SATA0_ACT_LED/UART9_RX_M1/I2S3_SDI_M1/GPIO4_C6_d, 234 MIPI_CSI_RX_D1P, 235 PWM14_M1/SPI3_CLK_M1/CAN1_RX_M1/PCIE30X2_CLKREQn_M2/I2S3_MCLK_M1/GPIO4_C2_d, 236 MIPI_CSI_RX_CLK0N, 237 PWM15_IR_M1/SPI3_MOSI_M1/CAN1_TX_M1/PCIE30X2_WAKEn_M2/I2S3_SCLK_M1/GPIO4_C3_d, 238 MIPI_CSI_RX_CLK0P, 239 LCDC_D2/VOP_BT656_D2_M0/SPI0_CS0_M1/PCIE30X1_CLKREQn_M1/I2S1_LRCK_TX_M2/GPIO2_D2_d, 240 MIPI_CSI_RX_CLK1N, 241 LCDC_D8/VOP_BT1120_D0/SPI1_CS0_M1/PCIE30X1_PERSTn_M1/SDMMC2_D0_M1/GPIO3_A1_d, 242 MIPI_CSI_RX_CLK1P, 243 LCDC_D1/VOP_BT656_D1_M0/SPI0_MOSI_M1/PCIE20_WAKEn_M1/I2S1_SCLK_TX_M2/GPIO2_D1_d, 244 GND50, 245 LCDC_D6/VOP_BT656_D6_M0/SPI2_MOSI_M1/PCIE30X2_PERSTn_M1/I2S1_SDI3_M2/GPIO2_D6_d, 246 LCDC_D0/VOP_BT656_D0_M0/SPI0_MISO_M1/PCIE20_CLKREQn_M1/I2S1_MCLK_M2/GPIO2_D0_d, 247 LCDC_D9/VOP_BT1120_D1/GMAC1_TXD2_M0/I2S3_MCLK_M0/SDMMC2_D1_M1/GPIO3_A2_d, 248 LCDC_D7/VOP_BT656_D7_M0/SPI2_MISO_M1/UART8_TX_M1/I2S1_SDO0_M2/GPIO2_D7_d, 249 LCDC_D22/PWM12_M0/GMAC1_TXEN_M0/UART3_TX_M1/PDM_SDI2_M2/GPIO3_B7_d, 250 LCDC_CLK/VOP_BT656_CLK_M0/SPI2_CLK_M1/UART8_RX_M1/I2S1_SDO1_M2/GPIO3_A0_d, 251 LCDC_D23/PWM13_M0/GMAC1_MCLKINOUT_M0/UART3_RX_M1/PDM_SDI3_M2/GPIO3_C0_d, 252 LCDC_D10/VOP_BT1120_D2/GMAC1_TXD3_M0/I2S3_SCLK_M0/SDMMC2_D2_M1/GPIO3_A3_d, 253 LCDC_D11/VOP_BT1120_D3/GMAC1_RXD2_M0/I2S3_LRCK_M0/SDMMC2_D3_M1/GPIO3_A4_d, 254 LCDC_D12/VOP_BT1120_D4/GMAC1_RXD3_M0/I2S3_SDO_M0/SDMMC2_CMD_M1/GPIO3_A5_d, 255 LCDC_D3/VOP_BT656_D3_M0/SPI0_CLK_M1/PCIE30X1_WAKEn_M1/I2S1_SDI0_M2/GPIO2_D3_d, 256 LCDC_D13/VOP_BT1120_CLK/GMAC1_TXCLK_M0/I2S3_SDI_M0/SDMMC2_CLK_M1/GPIO3_A6_d, 257 LCDC_DEN/VOP_BT1120_D15/SPI1_CLK_M1/UART5_RX_M1/I2S1_SCLK_RX_M2/GPIO3_C3_d, 258 LCDC_D14/VOP_BT1120_D5/GMAC1_RXCLK_M0/SDMMC2_DET_M1/GPIO3_A7_d, 259 PWM14_M0/VOP_PWM_M1/GMAC1_MDC_M0/UART7_TX_M1/PDM_CLK1_M2/GPIO3_C4_d, 260 GND51, 261 CON_INT_L_GPIO4_D2_d, 262 LCDC_D15/VOP_BT1120_D6/ETH1_REFCLKO_25M_M0/SDMMC2_PWREN_M1/GPIO3_B0_d, 263 LCDC_VSYNC/VOP_BT1120_D14/SPI1_MISO_M1/UART5_TX_M1/I2S1_SDO3_M2/GPIO3_C2_d, 264 LCDC_D17/VOP_BT1120_D8/GMAC1_RXD1_M0/UART4_TX_M1/PWM9_M0/GPIO3_B2_d, 265 I2C2_SDA_M1/EBC_GDSP/CAN2_RX_M0/ISP_FLASH_TRIGIN/VOP_BT656_CLK_M1/GPIO4_B4_d, 266 LCDC_D16/VOP_BT1120_D7/GMAC1_RXD0_M0/UART4_RX_M1/PWM8_M0/GPIO3_B1_d, 267 I2C2_SCL_M1/EBC_SDSHR/CAN2_TX_M0/I2S1_SDO3_M1/GPIO4_B5_d, 268 LCDC_D21/VOP_BT1120_D12/GMAC1_TXD1_M0/I2C3_SDA_M1/PWM11_IR_M0/GPIO3_B6_d, 269 LCDC_D20/VOP_BT1120_D11/GMAC1_TXD0_M0/I2C3_SCL_M1/PWM10_M0/GPIO3_B5_d, 270 LCDC_D18/VOP_BT1120_D9/GMAC1_RXDV_CRS_M0/I2C5_SCL_M0/PDM_SDI0_M2/GPIO3_B3_d, 271 GND22, 272 LCDC_D19/VOP_BT1120_D10/GMAC1_RXER_M0/I2C5_SDA_M0/PDM_SDI1_M2/GPIO3_B4_d, 273 CLK32K_OUT0_WIFI, 274 LCDC_HSYNC/VOP_BT1120_D13/SPI1_MOSI_M1/PCIE20_PERSTn_M1/I2S1_SDO2_M2/GPIO3_C1_d, 275 RK809_32KOUT_WIFI, 276 PWM15_IR_M0/SPDIF_TX_M1/GMAC1_MDIO_M0/UART7_RX_M1/I2S1_LRCK_RX_M2/GPIO3_C5_d, 277 GND23, 278 GND52, 279 CIF_D0/EBC_SDDO0/SDMMC2_D0_M0/I2S1_MCLK_M1/VOP_BT656_D0_M1/GPIO3_C6_d, 280 CIF_D5/EBC_SDDO5/SDMMC2_CLK_M0/I2S1_SDI1_M1/VOP_BT656_D5_M1/GPIO3_D3_d, 281 CIF_D1/EBC_SDDO1/SDMMC2_D1_M0/I2S1_SCLK_TX_M1/VOP_BT656_D1_M1/GPIO3_C7_d, 282 CIF_D2/EBC_SDDO2/SDMMC2_D2_M0/I2S1_LRCK_TX_M1/VOP_BT656_D2_M1/GPIO3_D0_d, 283 CIF_D4/EBC_SDDO4/SDMMC2_CMD_M0/I2S1_SDI0_M1/VOP_BT656_D4_M1/GPIO3_D2_d, 284 CIF_D3/EBC_SDDO3/SDMMC2_D3_M0/I2S1_SDO0_M1/VOP_BT656_D3_M1/GPIO3_D1_d, 285 WIFI_REG_ON_H_GPIO3_D5/CIF_D7, 286 GND53, 287 GND24, 288 CIF_D11/EBC_SDDO11/GMAC1_RXD2_M1/PDM_SDI1_M1/GPIO4_A1_d, 289 CIF_D10/EBC_SDDO10/GMAC1_TXCLK_M1/PDM_CLK1_M1/GPIO4_A0_d, 290 CIF_D6/EBC_SDDO6/SDMMC2_DET_M0/I2S1_SDI2_M1/VOP_BT656_D6_M1/GPIO3_D4_d, 291 CIF_D13/EBC_SDDO13/GMAC1_RXCLK_M1/UART7_RX_M2/PDM_SDI3_M1/GPIO4_A3_d, 292 CIF_D14/EBC_SDDO14/GMAC1_TXD0_M1/UART9_TX_M2/I2S2_LRCK_TX_M1/GPIO4_A4_d, 293 CIF_D12/EBC_SDDO12/GMAC1_RXD3_M1/UART7_TX_M2/PDM_SDI2_M1/GPIO4_A2_d, 294 CIF_D15/EBC_SDDO15/GMAC1_TXD1_M1/UART9_RX_M2/I2S2_LRCK_RX_M1/GPIO4_A5_d, 295 CIF_D9/EBC_SDDO9/GMAC1_TXD3_M1/UART1_RX_M1/PDM_SDI0_M1/GPIO3_D7_d, 296 ISP_FLASHTRIGOUT/EBC_SDCE0/GMAC1_TXEN_M1/SPI3_CS0_M0/I2S1_SCLK_RX_M1/GPIO4_A6_d, 297 CIF_D8/EBC_SDDO8/GMAC1_TXD2_M1/UART1_TX_M1/PDM_CLK0_M1/GPIO3_D6_d, 298 CAM_CLKOUT0/EBC_SDCE1/GMAC1_RXD0_M1/SPI3_CS1_M0/I2S1_LRCK_RX_M1/GPIO4_A7_d, 299 CAM_CLKOUT1/EBC_SDCE2/GMAC1_RXD1_M1/SPI3_MISO_M0/I2S1_SDO1_M1/GPIO4_B0_d, 300 ISP_PRELIGHT_TRIG/EBC_SDCE3/GMAC1_RXDV_CRS_M1/I2S1_SDO2_M1/GPIO4_B1_d, 301 GND25, 302 CIF_CLKIN/EBC_SDCLK/GMAC1_MCLKINOUT_M1/UART1_CTSn_M1/I2S2_SCLK_RX_M1/GPIO4_C1_d, 303 CIF_CLKOUT/EBC_GDCLK/PWM11_IR_M1/GPIO4_C0_d, 304 GND54, 305 GND26, 306 USB2_HOST3_DP, 307 CIF_VSYNC/EBC_SDOE/GMAC1_MDIO_M1/I2S2_SCLK_TX_M1/GPIO4_B7_d, 308 USB2_HOST3_DM, 309 CIF_HREF/EBC_SDLE/GMAC1_MDC_M1/UART1_RTSn_M1/I2S2_MCLK_M1/GPIO4_B6_d, 310 USB2_HOST2_DP, 311 GND27, 312 USB2_HOST2_DM, 313 I2C4_SCL_M0/EBC_GDOE/ETH1_REFCLKO_25M_M1/SPI3_CLK_M0/I2S2_SDO_M1/GPIO4_B3_d, 314 I2C4_SDA_M0/EBC_VCOM/GMAC1_RXER_M1/SPI3_MOSI_M0/I2S2_SDI_M1/GPIO4_B2_d

## CRYSTAL_0
designator Y?
CLASS: IC
pins: 1, 2 GND1, 3, 4 GND2

## CRYSTAL_2P
designator Y?
footprint 3215
pins: 1, 2

## CRYSTAL_4P
designator Y?
CLASS: IC
pins: 1, 2 GND1 (power), 3, 4 GND2 (power)

## DIODE BI-DIR TRIG
designator D?
footprint D0603/SMD
pins: 1, 2

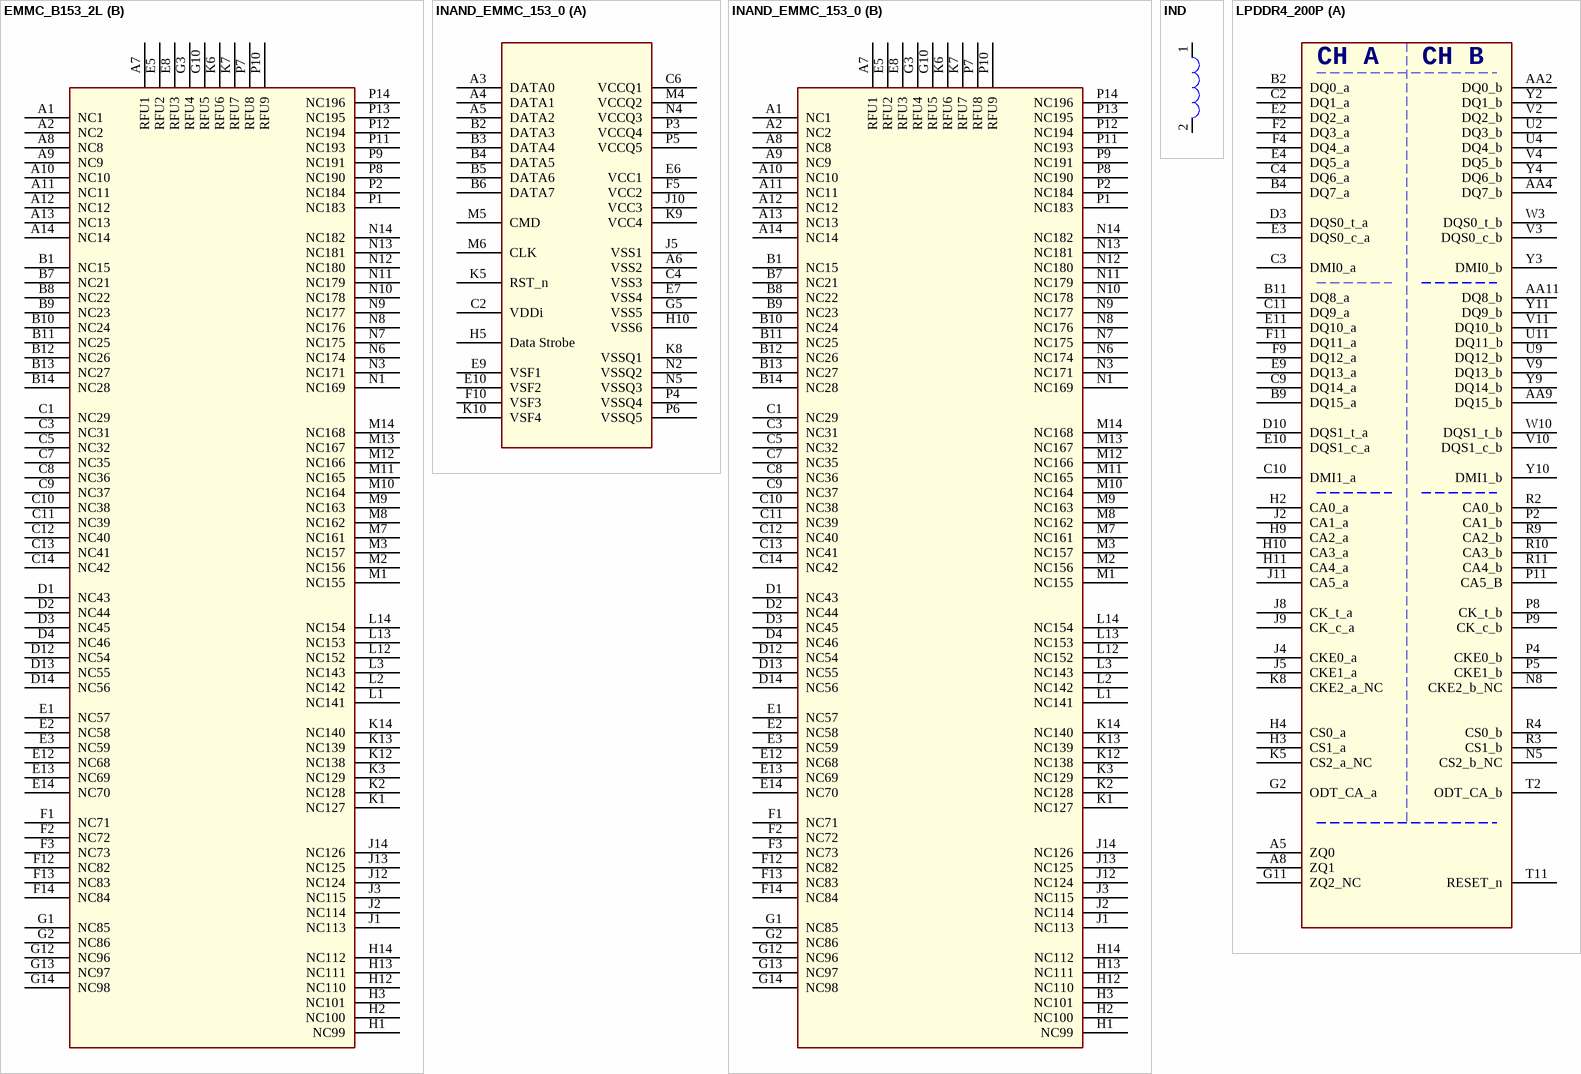
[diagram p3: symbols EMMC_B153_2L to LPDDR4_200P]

## EMMC_B153_2L
designator U?
part A pins: A3 DATA0, A4 DATA1, A5 DATA2, A6 VSS2, B2 DATA3, B3 DATA4, B4 DATA5, B5 DATA6, B6 DATA7, C2 VDDi, C4 VSS3, C6 VCCQ1, E6 VCC1, E7 VSS4, E9 VSF1, E10 VSF2, F5 VCC2, F10 VSF3, G5 VSS5, H5 Data Strobe, H10 VSS6, J5 VSS1, J10 VCC3, K5 RST_n, K8 VSSQ1, K9 VCC4, K10 VSF4, M4 VCCQ2, M5 CMD, M6 CLK, N2 VSSQ2, N4 VCCQ3, N5 VSSQ3, P3 VCCQ4, P4 VSSQ4, P5 VCCQ5, P6 VSSQ5
part B pins: A1 NC1, A2 NC2, A7 RFU1, A8 NC8, A9 NC9, A10 NC10, A11 NC11, A12 NC12, A13 NC13, A14 NC14, B1 NC15, B7 NC21, B8 NC22, B9 NC23, B10 NC24, B11 NC25, B12 NC26, B13 NC27, B14 NC28, C1 NC29, C3 NC31, C5 NC32, C7 NC35, C8 NC36, C9 NC37, C10 NC38, C11 NC39, C12 NC40, C13 NC41, C14 NC42, D1 NC43, D2 NC44, D3 NC45, D4 NC46, D12 NC54, D13 NC55, D14 NC56, E1 NC57, E2 NC58, E3 NC59, E5 RFU2, E8 RFU3, E12 NC68, E13 NC69, E14 NC70, F1 NC71, F2 NC72, F3 NC73, F12 NC82, F13 NC83, F14 NC84, G1 NC85, G2 NC86, G3 RFU4, G10 RFU5, G12 NC96, G13 NC97, G14 NC98, H1 NC99, H2 NC100, H3 NC101, H12 NC110, H13 NC111, H14 NC112, J1 NC113, J2 NC114, J3 NC115, J12 NC124, J13 NC125, J14 NC126, K1 NC127, K2 NC128, K3 NC129, K6 RFU6, K7 RFU7, K12 NC138, K13 NC139, K14 NC140, L1 NC141, L2 NC142, L3 NC143, L12 NC152, L13 NC153, L14 NC154, M1 NC155, M2 NC156, M3 NC157, M7 NC161, M8 NC162, M9 NC163, M10 NC164, M11 NC165, M12 NC166, M13 NC167, M14 NC168, N1 NC169, N3 NC171, N6 NC174, N7 NC175, N8 NC176, N9 NC177, N10 NC178, N11 NC179, N12 NC180, N13 NC181, N14 NC182, P1 NC183, P2 NC184, P7 RFU8, P8 NC190, P9 NC191, P10 RFU9, P11 NC193, P12 NC194, P13 NC195, P14 NC196

## INAND_EMMC_153_0
designator U?
part A pins: A3 DATA0, A4 DATA1, A5 DATA2, A6 VSS2, B2 DATA3, B3 DATA4, B4 DATA5, B5 DATA6, B6 DATA7, C2 VDDi, C4 VSS3, C6 VCCQ1, E6 VCC1, E7 VSS4, E9 VSF1, E10 VSF2, F5 VCC2, F10 VSF3, G5 VSS5, H5 Data Strobe, H10 VSS6, J5 VSS1, J10 VCC3, K5 RST_n, K8 VSSQ1, K9 VCC4, K10 VSF4, M4 VCCQ2, M5 CMD, M6 CLK, N2 VSSQ2, N4 VCCQ3, N5 VSSQ3, P3 VCCQ4, P4 VSSQ4, P5 VCCQ5, P6 VSSQ5
part B pins: A1 NC1, A2 NC2, A7 RFU1, A8 NC8, A9 NC9, A10 NC10, A11 NC11, A12 NC12, A13 NC13, A14 NC14, B1 NC15, B7 NC21, B8 NC22, B9 NC23, B10 NC24, B11 NC25, B12 NC26, B13 NC27, B14 NC28, C1 NC29, C3 NC31, C5 NC32, C7 NC35, C8 NC36, C9 NC37, C10 NC38, C11 NC39, C12 NC40, C13 NC41, C14 NC42, D1 NC43, D2 NC44, D3 NC45, D4 NC46, D12 NC54, D13 NC55, D14 NC56, E1 NC57, E2 NC58, E3 NC59, E5 RFU2, E8 RFU3, E12 NC68, E13 NC69, E14 NC70, F1 NC71, F2 NC72, F3 NC73, F12 NC82, F13 NC83, F14 NC84, G1 NC85, G2 NC86, G3 RFU4, G10 RFU5, G12 NC96, G13 NC97, G14 NC98, H1 NC99, H2 NC100, H3 NC101, H12 NC110, H13 NC111, H14 NC112, J1 NC113, J2 NC114, J3 NC115, J12 NC124, J13 NC125, J14 NC126, K1 NC127, K2 NC128, K3 NC129, K6 RFU6, K7 RFU7, K12 NC138, K13 NC139, K14 NC140, L1 NC141, L2 NC142, L3 NC143, L12 NC152, L13 NC153, L14 NC154, M1 NC155, M2 NC156, M3 NC157, M7 NC161, M8 NC162, M9 NC163, M10 NC164, M11 NC165, M12 NC166, M13 NC167, M14 NC168, N1 NC169, N3 NC171, N6 NC174, N7 NC175, N8 NC176, N9 NC177, N10 NC178, N11 NC179, N12 NC180, N13 NC181, N14 NC182, P1 NC183, P2 NC184, P7 RFU8, P8 NC190, P9 NC191, P10 RFU9, P11 NC193, P12 NC194, P13 NC195, P14 NC196

## IND
designator L?
CLASS: DISCRETE
pins: 1, 2

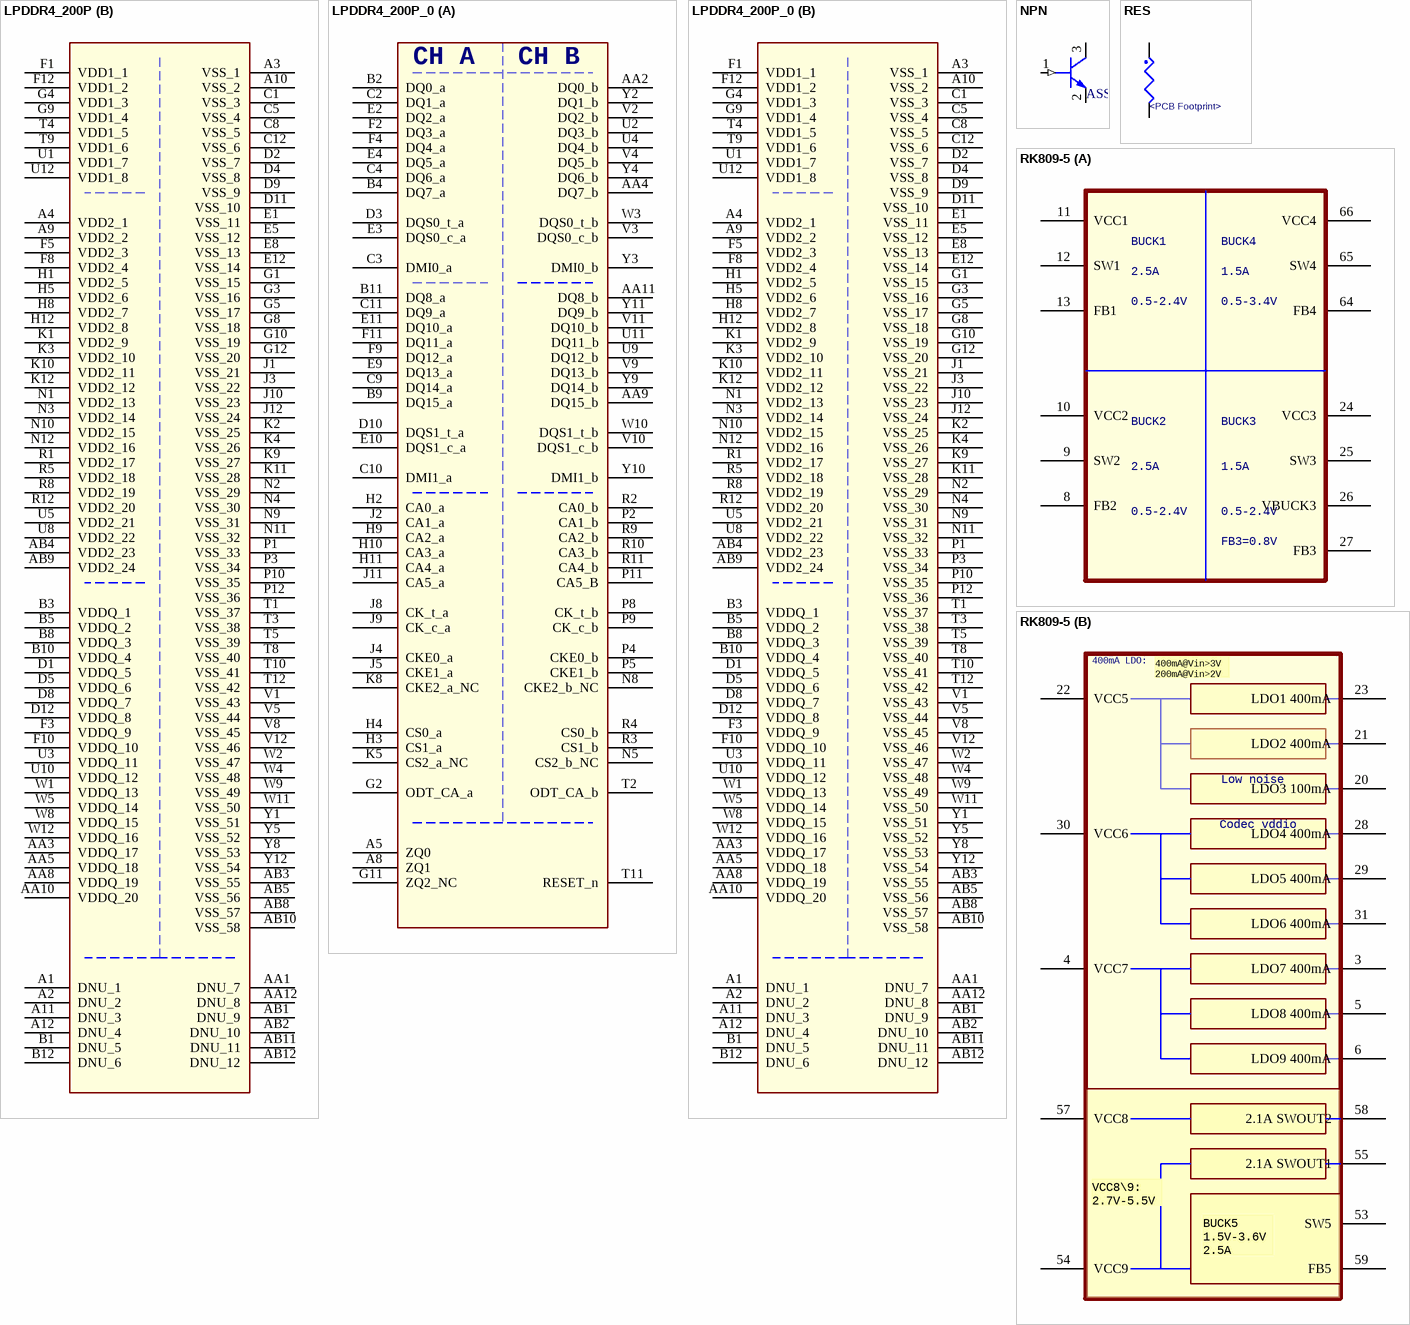
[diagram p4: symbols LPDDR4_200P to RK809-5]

## LPDDR4_200P
designator U?
part A pins: A5 ZQ0, A8 ZQ1, AA2 DQ0_b, AA4 DQ7_b, AA9 DQ15_b, AA11 DQ8_b, B2 DQ0_a, B4 DQ7_a, B9 DQ15_a, B11 DQ8_a, C2 DQ1_a, C3 DMI0_a, C4 DQ6_a, C9 DQ14_a, C10 DMI1_a, C11 DQ9_a, D3 DQS0_t_a, D10 DQS1_t_a, E2 DQ2_a, E3 DQS0_c_a, E4 DQ5_a, E9 DQ13_a, E10 DQS1_c_a, E11 DQ10_a, F2 DQ3_a, F4 DQ4_a, F9 DQ12_a, F11 DQ11_a, G2 ODT_CA_a, G11 ZQ2_NC, H2 CA0_a, H3 CS1_a, H4 CS0_a, H9 CA2_a, H10 CA3_a, H11 CA4_a, J2 CA1_a, J4 CKE0_a, J5 CKE1_a, J8 CK_t_a, J9 CK_c_a, J11 CA5_a, K5 CS2_a_NC, K8 CKE2_a_NC, N5 CS2_b_NC, N8 CKE2_b_NC, P2 CA1_b, P4 CKE0_b, P5 CKE1_b, P8 CK_t_b, P9 CK_c_b, P11 CA5_B, R2 CA0_b, R3 CS1_b, R4 CS0_b, R9 CA2_b, R10 CA3_b, R11 CA4_b, T2 ODT_CA_b, T11 RESET_n, U2 DQ3_b, U4 DQ4_b, U9 DQ12_b, U11 DQ11_b, V2 DQ2_b, V3 DQS0_c_b, V4 DQ5_b, V9 DQ13_b, V10 DQS1_c_b, V11 DQ10_b, W3 DQS0_t_b, W10 DQS1_t_b, Y2 DQ1_b, Y3 DMI0_b, Y4 DQ6_b, Y9 DQ14_b, Y10 DMI1_b, Y11 DQ9_b
part B pins: A1 DNU_1, A2 DNU_2, A3 VSS_1 (power), A4 VDD2_1 (power), A9 VDD2_2 (power), A10 VSS_2 (power), A11 DNU_3, A12 DNU_4, AA1 DNU_7, AA3 VDDQ_17 (power), AA5 VDDQ_18 (power), AA8 VDDQ_19 (power), AA10 VDDQ_20 (power), AA12 DNU_8, AB1 DNU_9, AB2 DNU_10, AB3 VSS_55 (power), AB4 VDD2_23 (power), AB5 VSS_56 (power), AB8 VSS_57 (power), AB9 VDD2_24 (power), AB10 VSS_58 (power), AB11 DNU_11, AB12 DNU_12, B1 DNU_5, B3 VDDQ_1 (power), B5 VDDQ_2 (power), B8 VDDQ_3 (power), B10 VDDQ_4 (power), B12 DNU_6, C1 VSS_3 (power), C5 VSS_4 (power), C8 VSS_5 (power), C12 VSS_6 (power), D1 VDDQ_5 (power), D2 VSS_7 (power), D4 VSS_8 (power), D5 VDDQ_6 (power), D8 VDDQ_7 (power), D9 VSS_9 (power), D11 VSS_10 (power), D12 VDDQ_8 (power), E1 VSS_11 (power), E5 VSS_12 (power), E8 VSS_13 (power), E12 VSS_14 (power), F1 VDD1_1 (power), F3 VDDQ_9 (power), F5 VDD2_3 (power), F8 VDD2_4 (power), F10 VDDQ_10 (power), F12 VDD1_2 (power), G1 VSS_15 (power), G3 VSS_16 (power), G4 VDD1_3 (power), G5 VSS_17 (power), G8 VSS_18 (power), G9 VDD1_4 (power), G10 VSS_19 (power), G12 VSS_20 (power), H1 VDD2_5 (power), H5 VDD2_6 (power), H8 VDD2_7 (power), H12 VDD2_8 (power), J1 VSS_21 (power), J3 VSS_22 (power), J10 VSS_23 (power), J12 VSS_24 (power), K1 VDD2_9 (power), K2 VSS_25 (power), K3 VDD2_10 (power), K4 VSS_26 (power), K9 VSS_27 (power), K10 VDD2_11 (power), K11 VSS_28 (power), K12 VDD2_12 (power), N1 VDD2_13 (power), N2 VSS_29 (power), N3 VDD2_14 (power), N4 VSS_30 (power), N9 VSS_31 (power), N10 VDD2_15 (power), N11 VSS_32 (power), N12 VDD2_16 (power), P1 VSS_33 (power), P3 VSS_34 (power), P10 VSS_35 (power), P12 VSS_36 (power), R1 VDD2_17 (power), R5 VDD2_18 (power), R8 VDD2_19 (power), R12 VDD2_20 (power), T1 VSS_37 (power), T3 VSS_38 (power), T4 VDD1_5 (power), T5 VSS_39 (power), T8 VSS_40 (power), T9 VDD1_6 (power), T10 VSS_41 (power), T12 VSS_42 (power), U1 VDD1_7 (power), U3 VDDQ_11 (power), U5 VDD2_21 (power), U8 VDD2_22 (power), U10 VDDQ_12 (power), U12 VDD1_8 (power), V1 VSS_43 (power), V5 VSS_44 (power), V8 VSS_45 (power), V12 VSS_46 (power), W1 VDDQ_13 (power), W2 VSS_47 (power), W4 VSS_48 (power), W5 VDDQ_14 (power), W8 VDDQ_15 (power), W9 VSS_49 (power), W11 VSS_50 (power), W12 VDDQ_16 (power), Y1 VSS_51 (power), Y5 VSS_52 (power), Y8 VSS_53 (power), Y12 VSS_54 (power)

## LPDDR4_200P_0
designator U?
part A pins: A5 ZQ0, A8 ZQ1, AA2 DQ0_b, AA4 DQ7_b, AA9 DQ15_b, AA11 DQ8_b, B2 DQ0_a, B4 DQ7_a, B9 DQ15_a, B11 DQ8_a, C2 DQ1_a, C3 DMI0_a, C4 DQ6_a, C9 DQ14_a, C10 DMI1_a, C11 DQ9_a, D3 DQS0_t_a, D10 DQS1_t_a, E2 DQ2_a, E3 DQS0_c_a, E4 DQ5_a, E9 DQ13_a, E10 DQS1_c_a, E11 DQ10_a, F2 DQ3_a, F4 DQ4_a, F9 DQ12_a, F11 DQ11_a, G2 ODT_CA_a, G11 ZQ2_NC, H2 CA0_a, H3 CS1_a, H4 CS0_a, H9 CA2_a, H10 CA3_a, H11 CA4_a, J2 CA1_a, J4 CKE0_a, J5 CKE1_a, J8 CK_t_a, J9 CK_c_a, J11 CA5_a, K5 CS2_a_NC, K8 CKE2_a_NC, N5 CS2_b_NC, N8 CKE2_b_NC, P2 CA1_b, P4 CKE0_b, P5 CKE1_b, P8 CK_t_b, P9 CK_c_b, P11 CA5_B, R2 CA0_b, R3 CS1_b, R4 CS0_b, R9 CA2_b, R10 CA3_b, R11 CA4_b, T2 ODT_CA_b, T11 RESET_n, U2 DQ3_b, U4 DQ4_b, U9 DQ12_b, U11 DQ11_b, V2 DQ2_b, V3 DQS0_c_b, V4 DQ5_b, V9 DQ13_b, V10 DQS1_c_b, V11 DQ10_b, W3 DQS0_t_b, W10 DQS1_t_b, Y2 DQ1_b, Y3 DMI0_b, Y4 DQ6_b, Y9 DQ14_b, Y10 DMI1_b, Y11 DQ9_b
part B pins: A1 DNU_1, A2 DNU_2, A3 VSS_1 (power), A4 VDD2_1 (power), A9 VDD2_2 (power), A10 VSS_2 (power), A11 DNU_3, A12 DNU_4, AA1 DNU_7, AA3 VDDQ_17 (power), AA5 VDDQ_18 (power), AA8 VDDQ_19 (power), AA10 VDDQ_20 (power), AA12 DNU_8, AB1 DNU_9, AB2 DNU_10, AB3 VSS_55 (power), AB4 VDD2_23 (power), AB5 VSS_56 (power), AB8 VSS_57 (power), AB9 VDD2_24 (power), AB10 VSS_58 (power), AB11 DNU_11, AB12 DNU_12, B1 DNU_5, B3 VDDQ_1 (power), B5 VDDQ_2 (power), B8 VDDQ_3 (power), B10 VDDQ_4 (power), B12 DNU_6, C1 VSS_3 (power), C5 VSS_4 (power), C8 VSS_5 (power), C12 VSS_6 (power), D1 VDDQ_5 (power), D2 VSS_7 (power), D4 VSS_8 (power), D5 VDDQ_6 (power), D8 VDDQ_7 (power), D9 VSS_9 (power), D11 VSS_10 (power), D12 VDDQ_8 (power), E1 VSS_11 (power), E5 VSS_12 (power), E8 VSS_13 (power), E12 VSS_14 (power), F1 VDD1_1 (power), F3 VDDQ_9 (power), F5 VDD2_3 (power), F8 VDD2_4 (power), F10 VDDQ_10 (power), F12 VDD1_2 (power), G1 VSS_15 (power), G3 VSS_16 (power), G4 VDD1_3 (power), G5 VSS_17 (power), G8 VSS_18 (power), G9 VDD1_4 (power), G10 VSS_19 (power), G12 VSS_20 (power), H1 VDD2_5 (power), H5 VDD2_6 (power), H8 VDD2_7 (power), H12 VDD2_8 (power), J1 VSS_21 (power), J3 VSS_22 (power), J10 VSS_23 (power), J12 VSS_24 (power), K1 VDD2_9 (power), K2 VSS_25 (power), K3 VDD2_10 (power), K4 VSS_26 (power), K9 VSS_27 (power), K10 VDD2_11 (power), K11 VSS_28 (power), K12 VDD2_12 (power), N1 VDD2_13 (power), N2 VSS_29 (power), N3 VDD2_14 (power), N4 VSS_30 (power), N9 VSS_31 (power), N10 VDD2_15 (power), N11 VSS_32 (power), N12 VDD2_16 (power), P1 VSS_33 (power), P3 VSS_34 (power), P10 VSS_35 (power), P12 VSS_36 (power), R1 VDD2_17 (power), R5 VDD2_18 (power), R8 VDD2_19 (power), R12 VDD2_20 (power), T1 VSS_37 (power), T3 VSS_38 (power), T4 VDD1_5 (power), T5 VSS_39 (power), T8 VSS_40 (power), T9 VDD1_6 (power), T10 VSS_41 (power), T12 VSS_42 (power), U1 VDD1_7 (power), U3 VDDQ_11 (power), U5 VDD2_21 (power), U8 VDD2_22 (power), U10 VDDQ_12 (power), U12 VDD1_8 (power), V1 VSS_43 (power), V5 VSS_44 (power), V8 VSS_45 (power), V12 VSS_46 (power), W1 VDDQ_13 (power), W2 VSS_47 (power), W4 VSS_48 (power), W5 VDDQ_14 (power), W8 VDDQ_15 (power), W9 VSS_49 (power), W11 VSS_50 (power), W12 VDDQ_16 (power), Y1 VSS_51 (power), Y5 VSS_52 (power), Y8 VSS_53 (power), Y12 VSS_54 (power)

## NPN
designator Q?
CLASS: IC
pins: 1 BASE (in), 2 EMITTER, 3 COLLECTOR

## RES
designator R?  PCB Footprint: <PCB Footprint>
CLASS: DISCRETE
pins: 1, 2

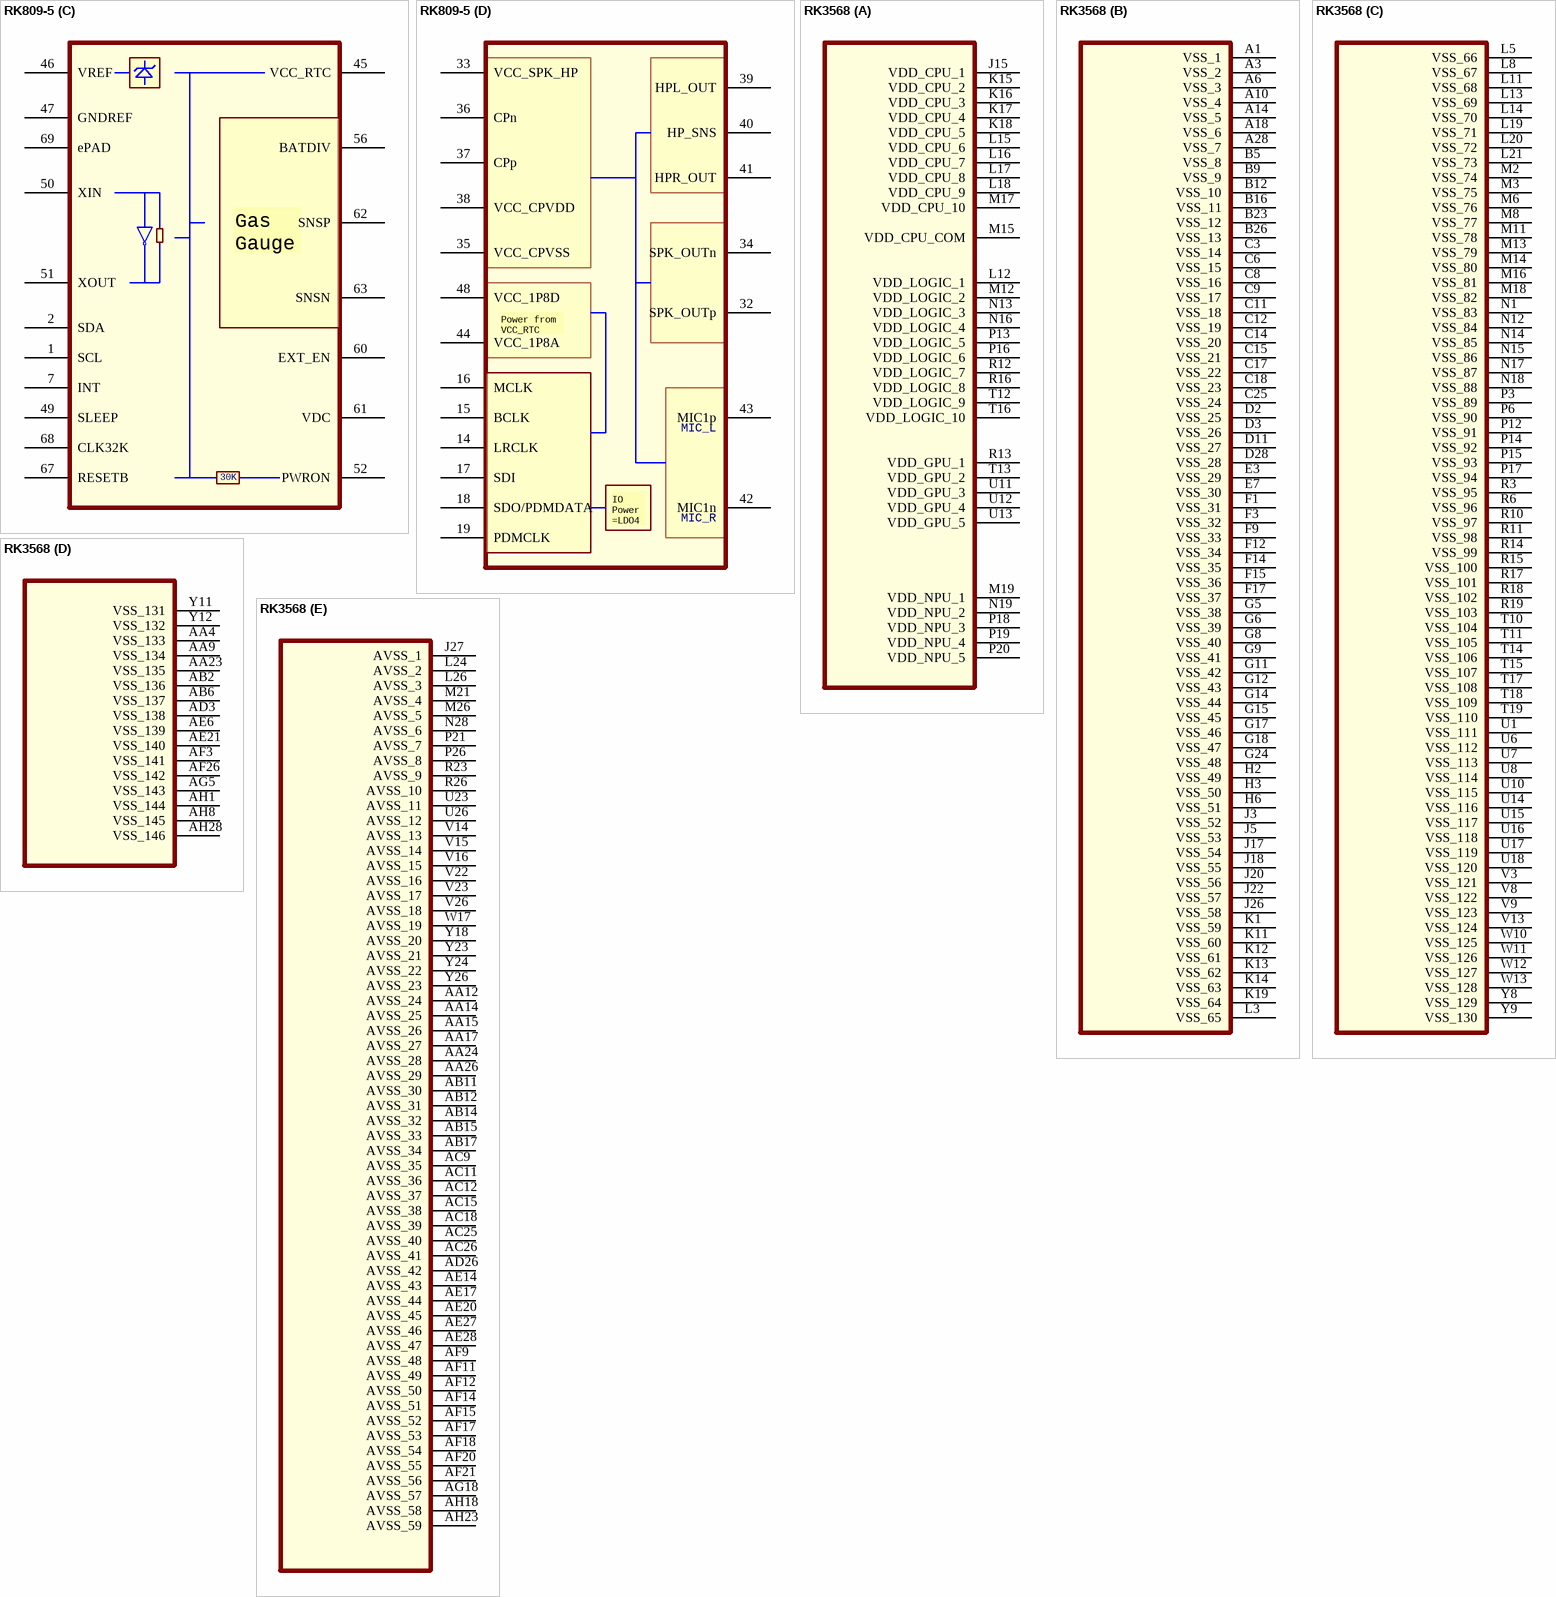
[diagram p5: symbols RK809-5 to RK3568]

## RK809-5
designator U?
footprint QFN68_7R00X7R00X0R80_T
part A pins: 8 FB2, 9 SW2, 10 VCC2, 11 VCC1, 12 SW1, 13 FB1, 24 VCC3, 25 SW3, 26 VBUCK3, 27 FB3, 64 FB4, 65 SW4, 66 VCC4
part B pins: 3 LDO7 400mA, 4 VCC7, 5 LDO8 400mA, 6 LDO9 400mA, 20 LDO3 100mA, 21 LDO2 400mA, 22 VCC5, 23 LDO1 400mA, 28 LDO4 400mA, 29 LDO5 400mA, 30 VCC6, 31 LDO6 400mA, 53 SW5, 54 VCC9, 55 2.1A SWOUT1, 57 VCC8, 58 2.1A SWOUT2, 59 FB5
part C pins: 1 SCL, 2 SDA, 7 INT, 45 VCC_RTC, 46 VREF, 47 GNDREF, 49 SLEEP, 50 XIN, 51 XOUT, 52 PWRON, 56 BATDIV, 60 EXT_EN, 61 VDC, 62 SNSP, 63 SNSN, 67 RESETB, 68 CLK32K, 69 ePAD
part D pins: 14 LRCLK, 15 BCLK, 16 MCLK, 17 SDI, 18 SDO/PDMDATA, 19 PDMCLK, 32 SPK_OUTp, 33 VCC_SPK_HP, 34 SPK_OUTn, 35 VCC_CPVSS, 36 CPn, 37 CPp, 38 VCC_CPVDD, 39 HPL_OUT, 40 HP_SNS, 41 HPR_OUT, 42 MIC1n, 43 MIC1p, 44 VCC_1P8A, 48 VCC_1P8D

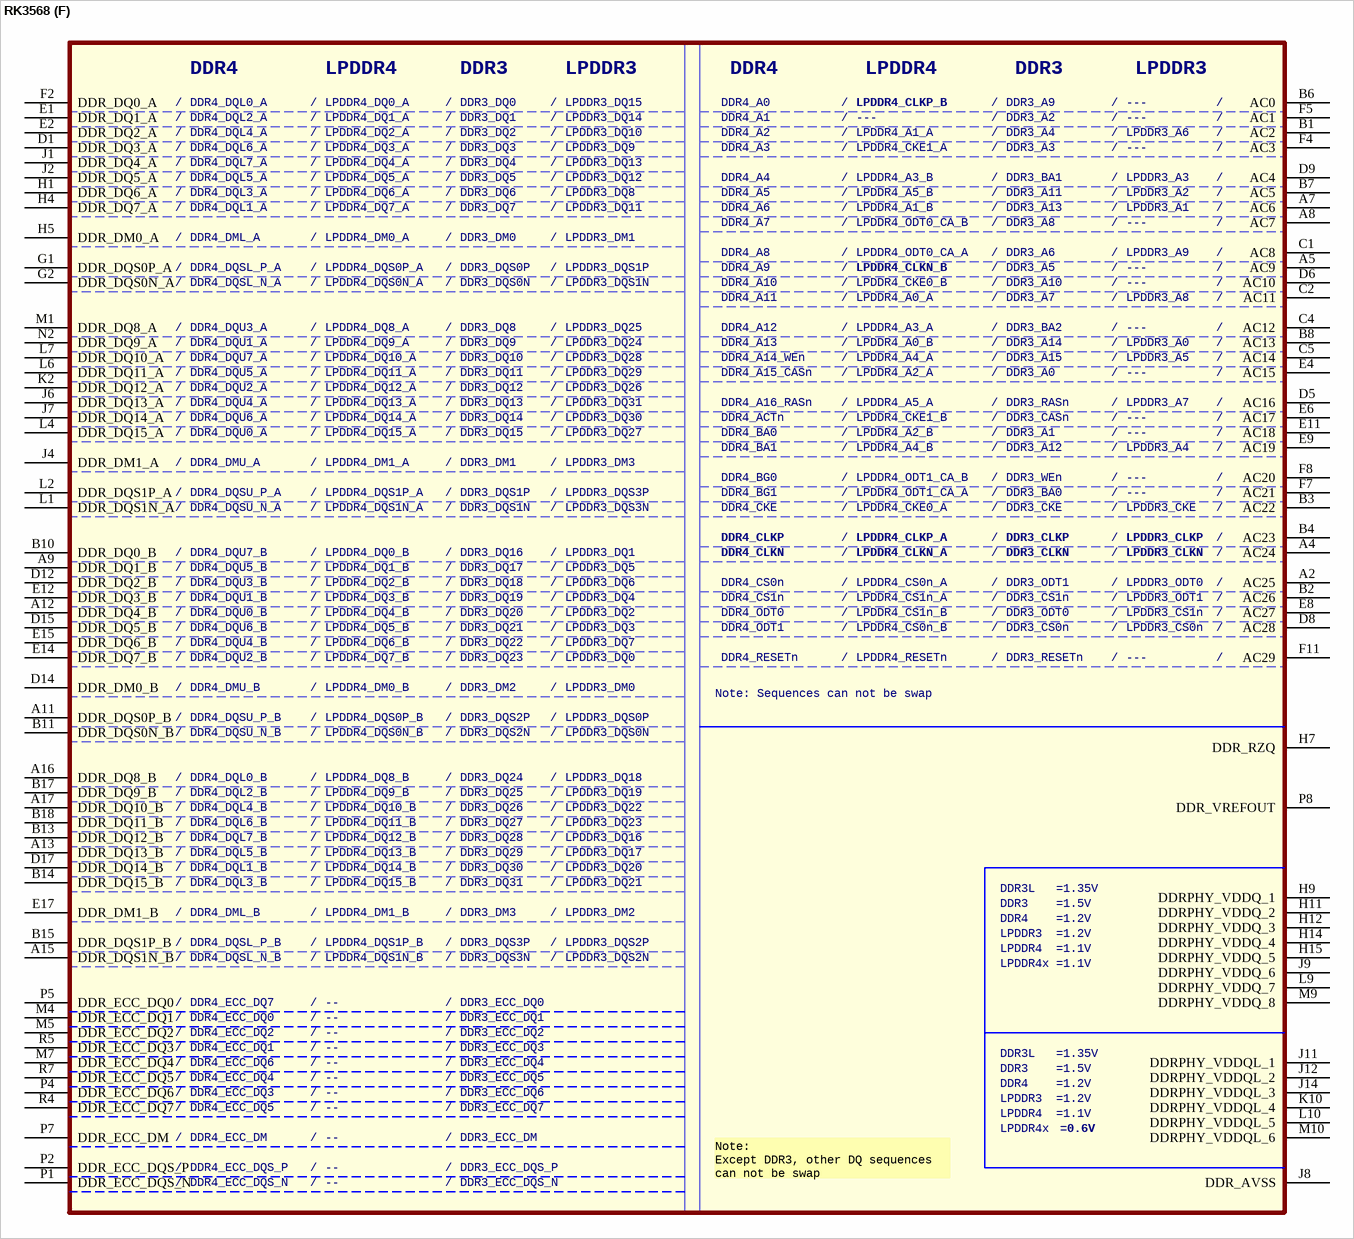
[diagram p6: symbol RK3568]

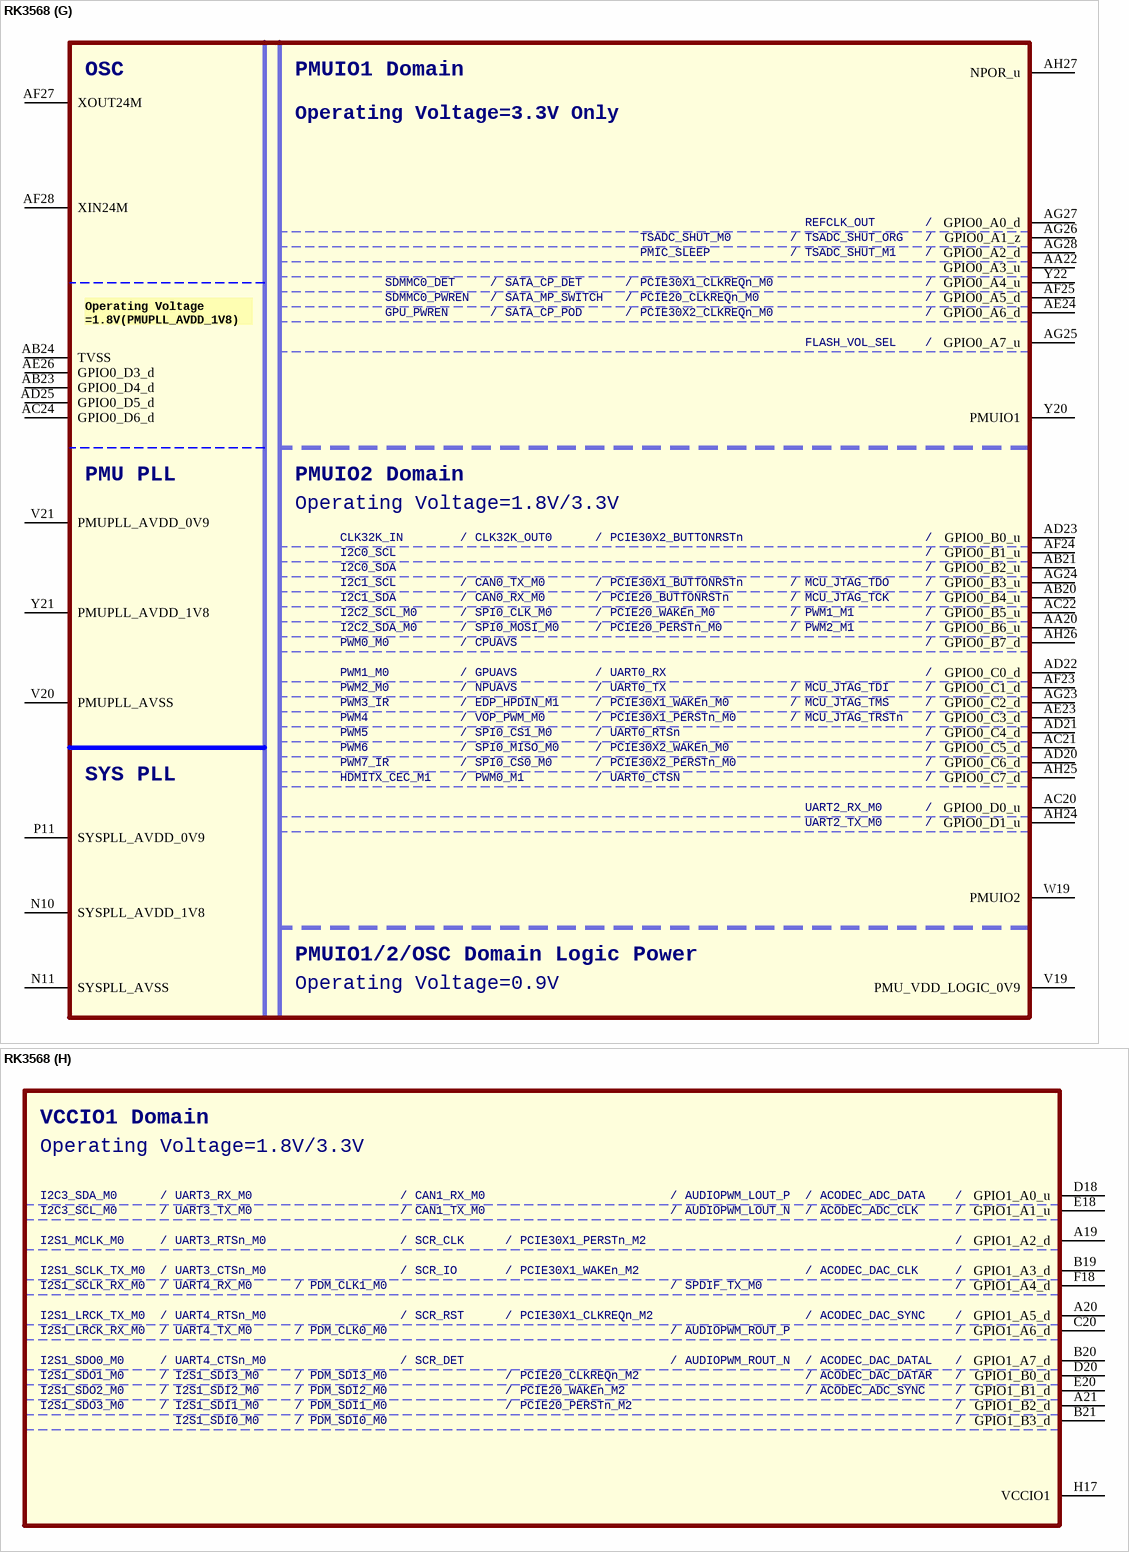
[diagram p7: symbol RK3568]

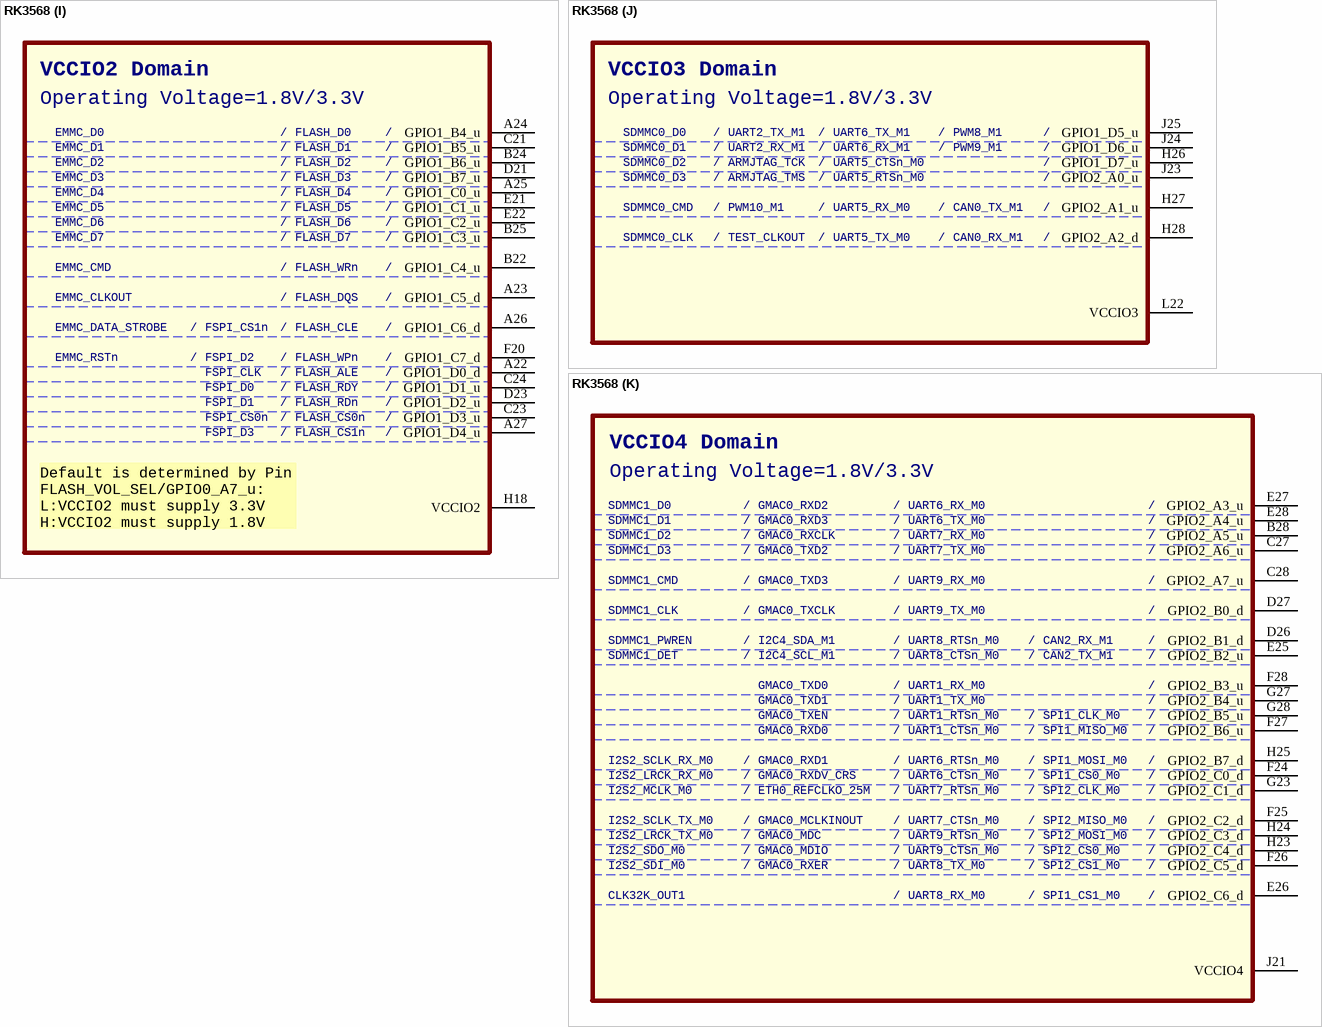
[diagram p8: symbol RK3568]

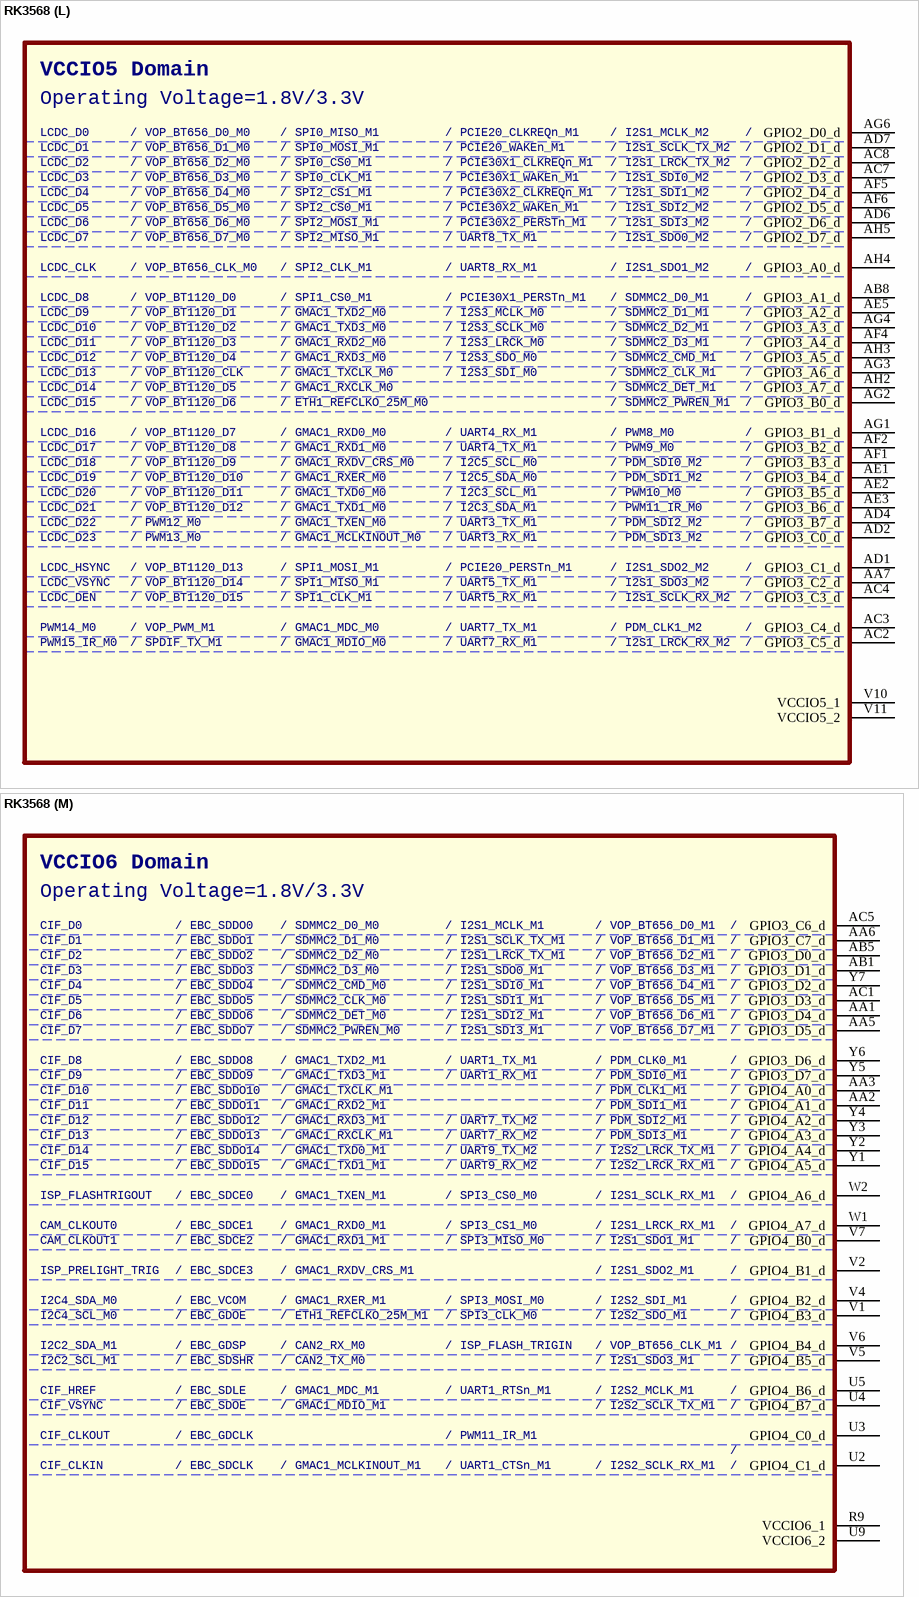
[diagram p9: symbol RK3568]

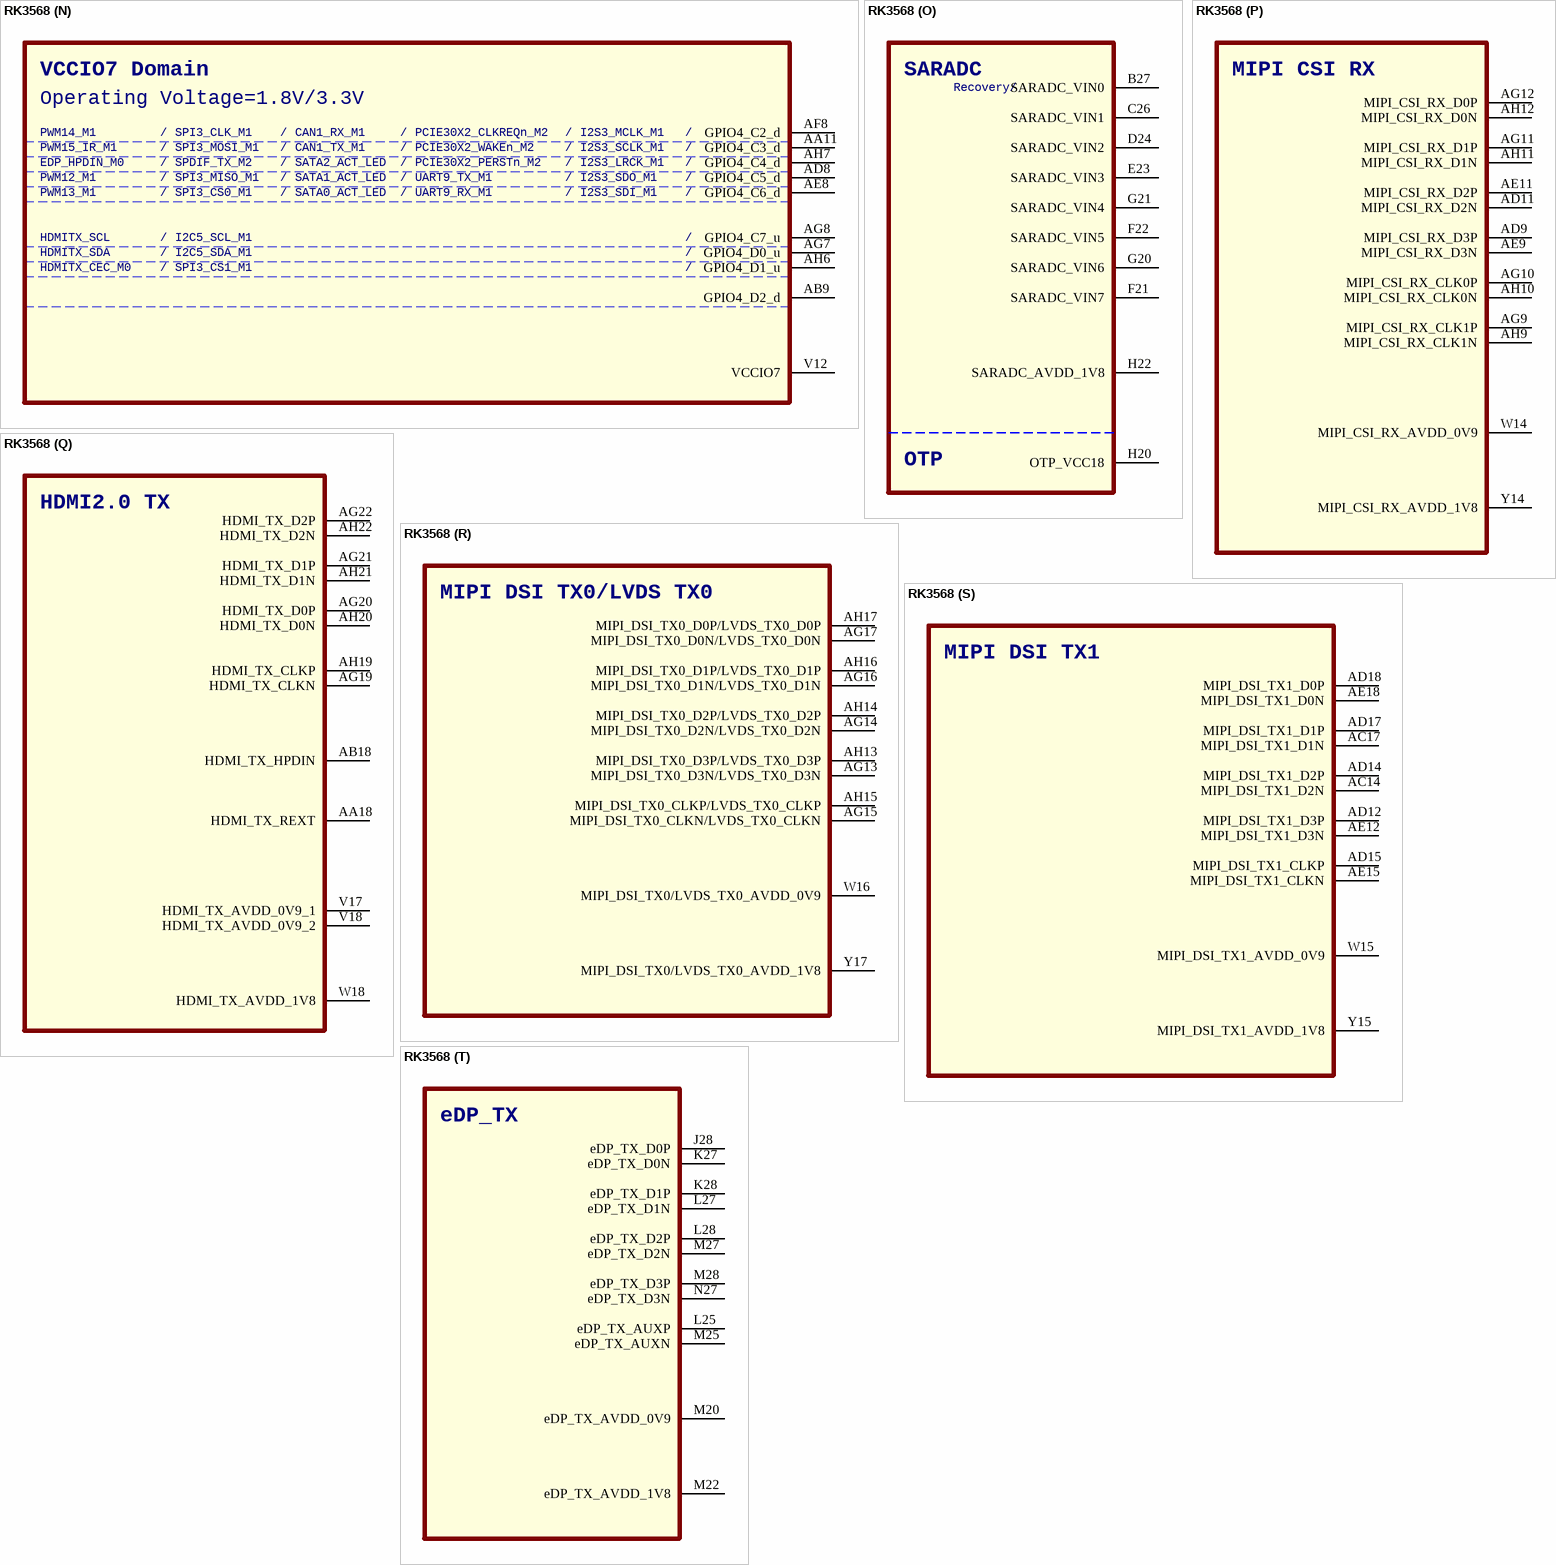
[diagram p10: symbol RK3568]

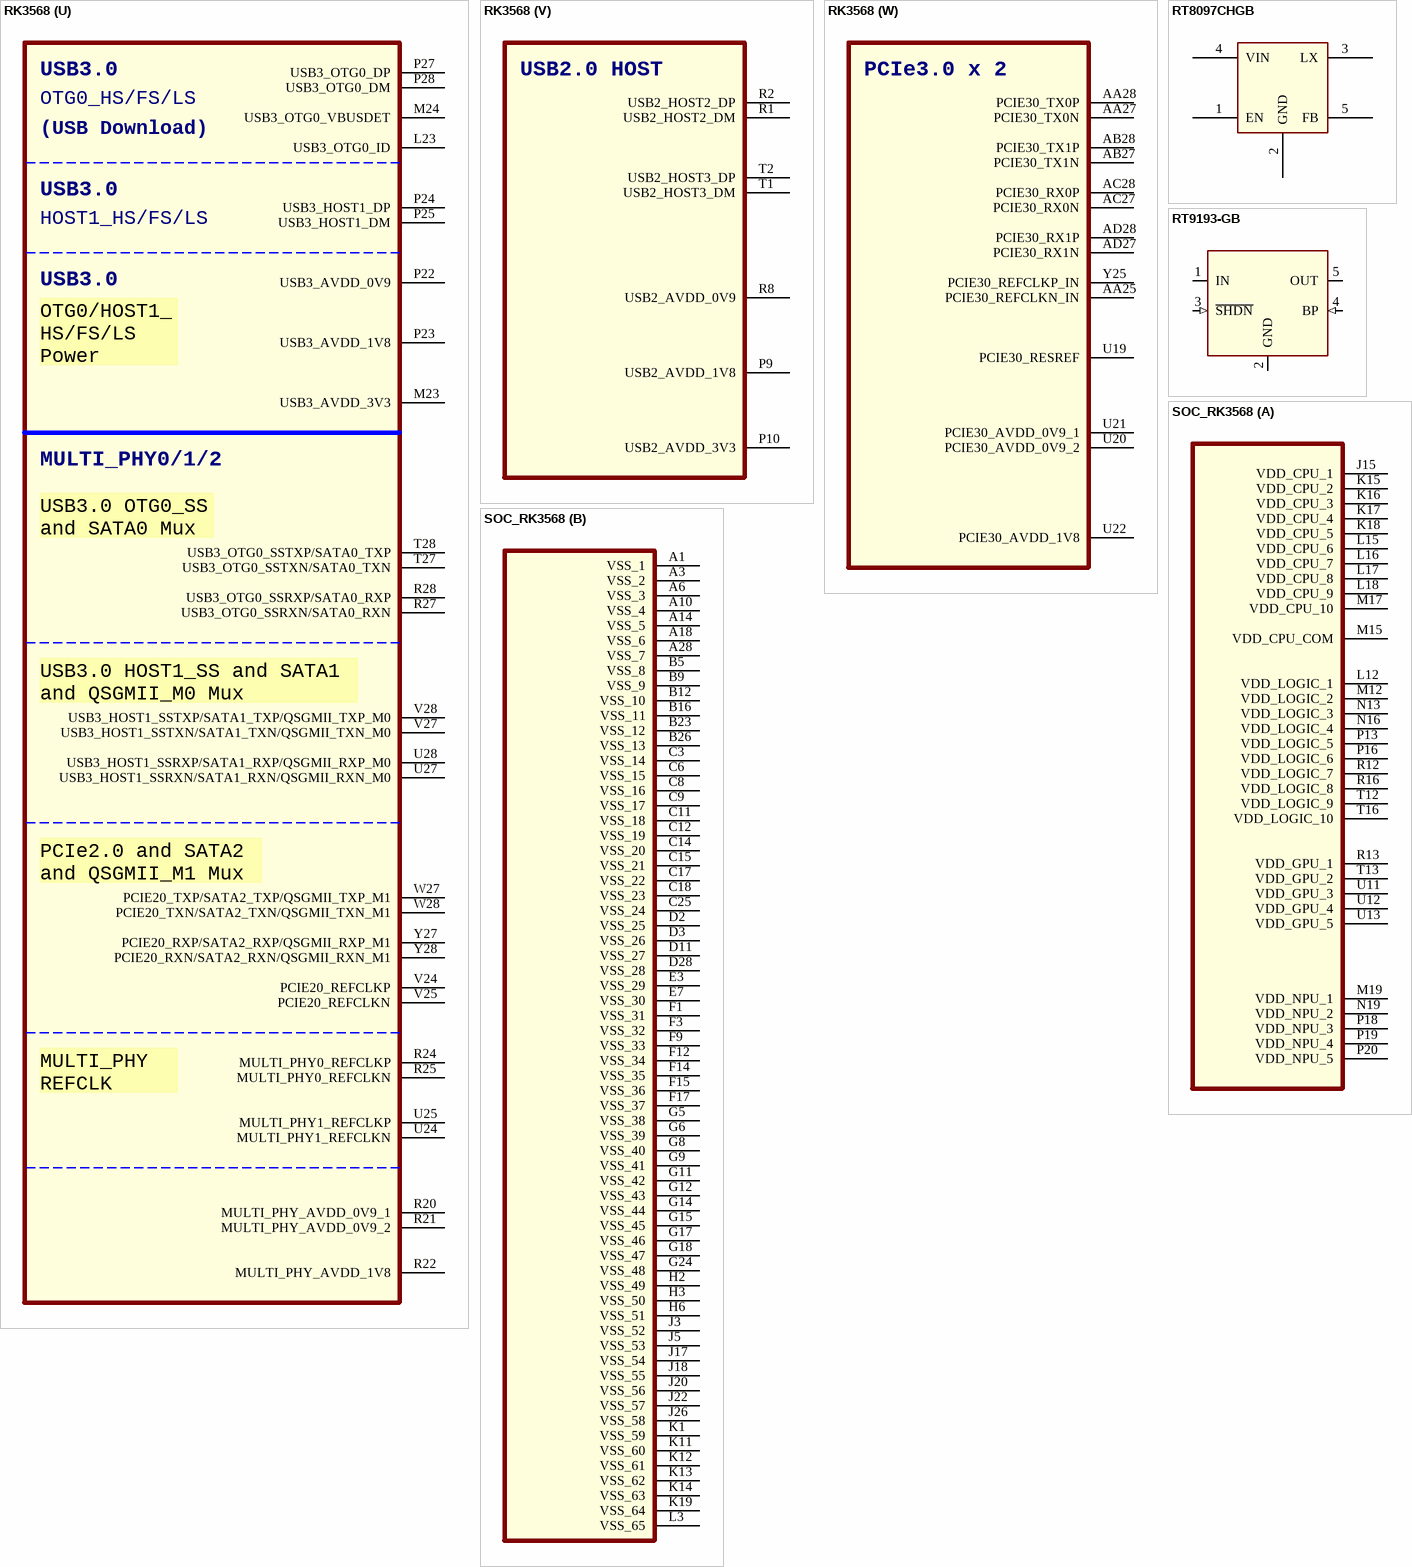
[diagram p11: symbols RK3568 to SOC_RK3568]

## RK3568
designator U?
SWAP_INFO: (S1+S2+S3+S4+S5+S6+S7+S8+S9+S10+S11+S12+S13+S14+S15+S16+S17+S18+S19+S20+S21+S22+S23); SPLIT_INST: TRUE
footprint BGA636_1
part A pins: J15 VDD_CPU_1, K15 VDD_CPU_2, K16 VDD_CPU_3, K17 VDD_CPU_4, K18 VDD_CPU_5, L12 VDD_LOGIC_1, L15 VDD_CPU_6, L16 VDD_CPU_7, L17 VDD_CPU_8, L18 VDD_CPU_9, M12 VDD_LOGIC_2, M15 VDD_CPU_COM, M17 VDD_CPU_10, M19 VDD_NPU_1, N13 VDD_LOGIC_3, N16 VDD_LOGIC_4, N19 VDD_NPU_2, P13 VDD_LOGIC_5, P16 VDD_LOGIC_6, P18 VDD_NPU_3, P19 VDD_NPU_4, P20 VDD_NPU_5, R12 VDD_LOGIC_7, R13 VDD_GPU_1, R16 VDD_LOGIC_8, T12 VDD_LOGIC_9, T13 VDD_GPU_2, T16 VDD_LOGIC_10, U11 VDD_GPU_3, U12 VDD_GPU_4, U13 VDD_GPU_5
part B pins: A1 VSS_1, A3 VSS_2, A6 VSS_3, A10 VSS_4, A14 VSS_5, A18 VSS_6, A28 VSS_7, B5 VSS_8, B9 VSS_9, B12 VSS_10, B16 VSS_11, B23 VSS_12, B26 VSS_13, C3 VSS_14, C6 VSS_15, C8 VSS_16, C9 VSS_17, C11 VSS_18, C12 VSS_19, C14 VSS_20, C15 VSS_21, C17 VSS_22, C18 VSS_23, C25 VSS_24, D2 VSS_25, D3 VSS_26, D11 VSS_27, D28 VSS_28, E3 VSS_29, E7 VSS_30, F1 VSS_31, F3 VSS_32, F9 VSS_33, F12 VSS_34, F14 VSS_35, F15 VSS_36, F17 VSS_37, G5 VSS_38, G6 VSS_39, G8 VSS_40, G9 VSS_41, G11 VSS_42, G12 VSS_43, G14 VSS_44, G15 VSS_45, G17 VSS_46, G18 VSS_47, G24 VSS_48, H2 VSS_49, H3 VSS_50, H6 VSS_51, J3 VSS_52, J5 VSS_53, J17 VSS_54, J18 VSS_55, J20 VSS_56, J22 VSS_57, J26 VSS_58, K1 VSS_59, K11 VSS_60, K12 VSS_61, K13 VSS_62, K14 VSS_63, K19 VSS_64, L3 VSS_65
part C pins: L5 VSS_66, L8 VSS_67, L11 VSS_68, L13 VSS_69, L14 VSS_70, L19 VSS_71, L20 VSS_72, L21 VSS_73, M2 VSS_74, M3 VSS_75, M6 VSS_76, M8 VSS_77, M11 VSS_78, M13 VSS_79, M14 VSS_80, M16 VSS_81, M18 VSS_82, N1 VSS_83, N12 VSS_84, N14 VSS_85, N15 VSS_86, N17 VSS_87, N18 VSS_88, P3 VSS_89, P6 VSS_90, P12 VSS_91, P14 VSS_92, P15 VSS_93, P17 VSS_94, R3 VSS_95, R6 VSS_96, R10 VSS_97, R11 VSS_98, R14 VSS_99, R15 VSS_100, R17 VSS_101, R18 VSS_102, R19 VSS_103, T10 VSS_104, T11 VSS_105, T14 VSS_106, T15 VSS_107, T17 VSS_108, T18 VSS_109, T19 VSS_110, U1 VSS_111, U6 VSS_112, U7 VSS_113, U8 VSS_114, U10 VSS_115, U14 VSS_116, U15 VSS_117, U16 VSS_118, U17 VSS_119, U18 VSS_120, V3 VSS_121, V8 VSS_122, V9 VSS_123, V13 VSS_124, W10 VSS_125, W11 VSS_126, W12 VSS_127, W13 VSS_128, Y8 VSS_129, Y9 VSS_130
part D pins: AA4 VSS_133, AA9 VSS_134, AA23 VSS_135, AB2 VSS_136, AB6 VSS_137, AD3 VSS_138, AE6 VSS_139, AE21 VSS_140, AF3 VSS_141, AF26 VSS_142, AG5 VSS_143, AH1 VSS_144, AH8 VSS_145, AH28 VSS_146, Y11 VSS_131, Y12 VSS_132
part E pins: AA12 AVSS_24, AA14 AVSS_25, AA15 AVSS_26, AA17 AVSS_27, AA24 AVSS_28, AA26 AVSS_29, AB11 AVSS_30, AB12 AVSS_31, AB14 AVSS_32, AB15 AVSS_33, AB17 AVSS_34, AC9 AVSS_35, AC11 AVSS_36, AC12 AVSS_37, AC15 AVSS_38, AC18 AVSS_39, AC25 AVSS_40, AC26 AVSS_41, AD26 AVSS_42, AE14 AVSS_43, AE17 AVSS_44, AE20 AVSS_45, AE27 AVSS_46, AE28 AVSS_47, AF9 AVSS_48, AF11 AVSS_49, AF12 AVSS_50, AF14 AVSS_51, AF15 AVSS_52, AF17 AVSS_53, AF18 AVSS_54, AF20 AVSS_55, AF21 AVSS_56, AG18 AVSS_57, AH18 AVSS_58, AH23 AVSS_59, J27 AVSS_1, L24 AVSS_2, L26 AVSS_3, M21 AVSS_4, M26 AVSS_5, N28 AVSS_6, P21 AVSS_7, P26 AVSS_8, R23 AVSS_9, R26 AVSS_10, U23 AVSS_11, U26 AVSS_12, V14 AVSS_13, V15 AVSS_14, V16 AVSS_15, V22 AVSS_16, V23 AVSS_17, V26 AVSS_18, W17 AVSS_19, Y18 AVSS_20, Y23 AVSS_21, Y24 AVSS_22, Y26 AVSS_23
part F pins: A2 AC25, A4 AC24, A5 AC9, A7 AC6, A8 AC7, A9 DDR_DQ1_B, A11 DDR_DQS0P_B, A12 DDR_DQ4_B, A13 DDR_DQ13_B, A15 DDR_DQS1N_B, A16 DDR_DQ8_B, A17 DDR_DQ10_B, B1 AC2, B2 AC26, B3 AC22, B4 AC23, B6 AC0, B7 AC5, B8 AC13, B10 DDR_DQ0_B, B11 DDR_DQS0N_B, B13 DDR_DQ12_B, B14 DDR_DQ15_B, B15 DDR_DQS1P_B, B17 DDR_DQ9_B, B18 DDR_DQ11_B, C1 AC8, C2 AC11, C4 AC12, C5 AC14, D1 DDR_DQ3_A, D5 AC16, D6 AC10, D8 AC28, D9 AC4, D12 DDR_DQ2_B, D14 DDR_DM0_B, D15 DDR_DQ5_B, D17 DDR_DQ14_B, E1 DDR_DQ1_A, E2 DDR_DQ2_A, E4 AC15, E6 AC17, E8 AC27, E9 AC19, E11 AC18, E12 DDR_DQ3_B, E14 DDR_DQ7_B, E15 DDR_DQ6_B, E17 DDR_DM1_B, F2 DDR_DQ0_A, F4 AC3, F5 AC1, F7 AC21, F8 AC20, F11 AC29, G1 DDR_DQS0P_A, G2 DDR_DQS0N_A, H1 DDR_DQ6_A, H4 DDR_DQ7_A, H5 DDR_DM0_A, H7 DDR_RZQ, H9 DDRPHY_VDDQ_1, H11 DDRPHY_VDDQ_2, H12 DDRPHY_VDDQ_3, H14 DDRPHY_VDDQ_4, H15 DDRPHY_VDDQ_5, J1 DDR_DQ4_A, J2 DDR_DQ5_A, J4 DDR_DM1_A, J6 DDR_DQ13_A, J7 DDR_DQ14_A, J8 DDR_AVSS, J9 DDRPHY_VDDQ_6, J11 DDRPHY_VDDQL_1, J12 DDRPHY_VDDQL_2, J14 DDRPHY_VDDQL_3, K2 DDR_DQ12_A, K10 DDRPHY_VDDQL_4, L1 DDR_DQS1N_A, L2 DDR_DQS1P_A, L4 DDR_DQ15_A, L6 DDR_DQ11_A, L7 DDR_DQ10_A, L9 DDRPHY_VDDQ_7, L10 DDRPHY_VDDQL_5, M1 DDR_DQ8_A, M4 DDR_ECC_DQ1, M5 DDR_ECC_DQ2, M7 DDR_ECC_DQ4, M9 DDRPHY_VDDQ_8, M10 DDRPHY_VDDQL_6, N2 DDR_DQ9_A, P1 DDR_ECC_DQS_N, P2 DDR_ECC_DQS_P, P4 DDR_ECC_DQ6, P5 DDR_ECC_DQ0, P7 DDR_ECC_DM, P8 DDR_VREFOUT, R4 DDR_ECC_DQ7, R5 DDR_ECC_DQ3, R7 DDR_ECC_DQ5
part G pins: AA20 GPIO0_B6_u, AA22 GPIO0_A3_u, AB20 GPIO0_B4_u, AB21 GPIO0_B2_u, AB23 GPIO0_D4_d, AB24 TVSS, AC20 GPIO0_D0_u, AC21 GPIO0_C5_d, AC22 GPIO0_B5_u, AC24 GPIO0_D6_d, AD20 GPIO0_C6_d, AD21 GPIO0_C4_d, AD22 GPIO0_C0_d, AD23 GPIO0_B0_u, AD25 GPIO0_D5_d, AE23 GPIO0_C3_d, AE24 GPIO0_A6_d, AE26 GPIO0_D3_d, AF23 GPIO0_C1_d, AF24 GPIO0_B1_u, AF25 GPIO0_A5_d, AF27 XOUT24M, AF28 XIN24M, AG23 GPIO0_C2_d, AG24 GPIO0_B3_u, AG25 GPIO0_A7_u, AG26 GPIO0_A1_z, AG27 GPIO0_A0_d, AG28 GPIO0_A2_d, AH24 GPIO0_D1_u, AH25 GPIO0_C7_d, AH26 GPIO0_B7_d, AH27 NPOR_u, N10 SYSPLL_AVDD_1V8, N11 SYSPLL_AVSS, P11 SYSPLL_AVDD_0V9, V19 PMU_VDD_LOGIC_0V9, V20 PMUPLL_AVSS, V21 PMUPLL_AVDD_0V9, W19 PMUIO2, Y20 PMUIO1, Y21 PMUPLL_AVDD_1V8, Y22 GPIO0_A4_u
part H pins: A19 GPIO1_A2_d, A20 GPIO1_A5_d, A21 GPIO1_B2_d, B19 GPIO1_A3_d, B20 GPIO1_A7_d, B21 GPIO1_B3_d, C20 GPIO1_A6_d, D18 GPIO1_A0_u, D20 GPIO1_B0_d, E18 GPIO1_A1_u, E20 GPIO1_B1_d, F18 GPIO1_A4_d, H17 VCCIO1
part I pins: A22 GPIO1_D0_d, A23 GPIO1_C5_d, A24 GPIO1_B4_u, A25 GPIO1_C0_u, A26 GPIO1_C6_d, A27 GPIO1_D4_u, B22 GPIO1_C4_u, B24 GPIO1_B6_u, B25 GPIO1_C3_u, C21 GPIO1_B5_u, C23 GPIO1_D3_u, C24 GPIO1_D1_u, D21 GPIO1_B7_u, D23 GPIO1_D2_u, E21 GPIO1_C1_u, E22 GPIO1_C2_u, F20 GPIO1_C7_d, H18 VCCIO2
part J pins: H26 GPIO1_D7_u, H27 GPIO2_A1_u, H28 GPIO2_A2_d, J23 GPIO2_A0_u, J24 GPIO1_D6_u, J25 GPIO1_D5_u, L22 VCCIO3
part K pins: B28 GPIO2_A5_u, C27 GPIO2_A6_u, C28 GPIO2_A7_u, D26 GPIO2_B1_d, D27 GPIO2_B0_d, E25 GPIO2_B2_u, E26 GPIO2_C6_d, E27 GPIO2_A3_u, E28 GPIO2_A4_u, F24 GPIO2_C0_d, F25 GPIO2_C2_d, F26 GPIO2_C5_d, F27 GPIO2_B6_u, F28 GPIO2_B3_u, G23 GPIO2_C1_d, G27 GPIO2_B4_u, G28 GPIO2_B5_u, H23 GPIO2_C4_d, H24 GPIO2_C3_d, H25 GPIO2_B7_d, J21 VCCIO4
part L pins: AA7 GPIO3_C2_d, AB8 GPIO3_A1_d, AC2 GPIO3_C5_d, AC3 GPIO3_C4_d, AC4 GPIO3_C3_d, AC7 GPIO2_D3_d, AC8 GPIO2_D2_d, AD1 GPIO3_C1_d, AD2 GPIO3_C0_d, AD4 GPIO3_B7_d, AD6 GPIO2_D6_d, AD7 GPIO2_D1_d, AE1 GPIO3_B4_d, AE2 GPIO3_B5_d, AE3 GPIO3_B6_d, AE5 GPIO3_A2_d, AF1 GPIO3_B3_d, AF2 GPIO3_B2_d, AF4 GPIO3_A4_d, AF5 GPIO2_D4_d, AF6 GPIO2_D5_d, AG1 GPIO3_B1_d, AG2 GPIO3_B0_d, AG3 GPIO3_A6_d, AG4 GPIO3_A3_d, AG6 GPIO2_D0_d, AH2 GPIO3_A7_d, AH3 GPIO3_A5_d, AH4 GPIO3_A0_d, AH5 GPIO2_D7_d, V10 VCCIO5_1, V11 VCCIO5_2
part M pins: AA1 GPIO3_D4_d, AA2 GPIO4_A1_d, AA3 GPIO4_A0_d, AA5 GPIO3_D5_d, AA6 GPIO3_C7_d, AB1 GPIO3_D1_d, AB5 GPIO3_D0_d, AC1 GPIO3_D3_d, AC5 GPIO3_C6_d, R9 VCCIO6_1, U2 GPIO4_C1_d, U3 GPIO4_C0_d, U4 GPIO4_B7_d, U5 GPIO4_B6_d, U9 VCCIO6_2, V1 GPIO4_B3_d, V2 GPIO4_B1_d, V4 GPIO4_B2_d, V5 GPIO4_B5_d, V6 GPIO4_B4_d, V7 GPIO4_B0_d, W1 GPIO4_A7_d, W2 GPIO4_A6_d, Y1 GPIO4_A5_d, Y2 GPIO4_A4_d, Y3 GPIO4_A3_d, Y4 GPIO4_A2_d, Y5 GPIO3_D7_d, Y6 GPIO3_D6_d, Y7 GPIO3_D2_d
part N pins: AA11 GPIO4_C3_d, AB9 GPIO4_D2_d, AD8 GPIO4_C5_d, AE8 GPIO4_C6_d, AF8 GPIO4_C2_d, AG7 GPIO4_D0_u, AG8 GPIO4_C7_u, AH6 GPIO4_D1_u, AH7 GPIO4_C4_d, V12 VCCIO7
part O pins: B27 SARADC_VIN0, C26 SARADC_VIN1, D24 SARADC_VIN2, E23 SARADC_VIN3, F21 SARADC_VIN7, F22 SARADC_VIN5, G20 SARADC_VIN6, G21 SARADC_VIN4, H20 OTP_VCC18, H22 SARADC_AVDD_1V8
part P pins: AD9 MIPI_CSI_RX_D3P, AD11 MIPI_CSI_RX_D2N, AE9 MIPI_CSI_RX_D3N, AE11 MIPI_CSI_RX_D2P, AG9 MIPI_CSI_RX_CLK1P, AG10 MIPI_CSI_RX_CLK0P, AG11 MIPI_CSI_RX_D1P, AG12 MIPI_CSI_RX_D0P, AH9 MIPI_CSI_RX_CLK1N, AH10 MIPI_CSI_RX_CLK0N, AH11 MIPI_CSI_RX_D1N, AH12 MIPI_CSI_RX_D0N, W14 MIPI_CSI_RX_AVDD_0V9, Y14 MIPI_CSI_RX_AVDD_1V8
part Q pins: AA18 HDMI_TX_REXT, AB18 HDMI_TX_HPDIN, AG19 HDMI_TX_CLKN, AG20 HDMI_TX_D0P, AG21 HDMI_TX_D1P, AG22 HDMI_TX_D2P, AH19 HDMI_TX_CLKP, AH20 HDMI_TX_D0N, AH21 HDMI_TX_D1N, AH22 HDMI_TX_D2N, V17 HDMI_TX_AVDD_0V9_1, V18 HDMI_TX_AVDD_0V9_2, W18 HDMI_TX_AVDD_1V8
part R pins: AG13 MIPI_DSI_TX0_D3N/LVDS_TX0_D3N, AG14 MIPI_DSI_TX0_D2N/LVDS_TX0_D2N, AG15 MIPI_DSI_TX0_CLKN/LVDS_TX0_CLKN, AG16 MIPI_DSI_TX0_D1N/LVDS_TX0_D1N, AG17 MIPI_DSI_TX0_D0N/LVDS_TX0_D0N, AH13 MIPI_DSI_TX0_D3P/LVDS_TX0_D3P, AH14 MIPI_DSI_TX0_D2P/LVDS_TX0_D2P, AH15 MIPI_DSI_TX0_CLKP/LVDS_TX0_CLKP, AH16 MIPI_DSI_TX0_D1P/LVDS_TX0_D1P, AH17 MIPI_DSI_TX0_D0P/LVDS_TX0_D0P, W16 MIPI_DSI_TX0/LVDS_TX0_AVDD_0V9, Y17 MIPI_DSI_TX0/LVDS_TX0_AVDD_1V8
part S pins: AC14 MIPI_DSI_TX1_D2N, AC17 MIPI_DSI_TX1_D1N, AD12 MIPI_DSI_TX1_D3P, AD14 MIPI_DSI_TX1_D2P, AD15 MIPI_DSI_TX1_CLKP, AD17 MIPI_DSI_TX1_D1P, AD18 MIPI_DSI_TX1_D0P, AE12 MIPI_DSI_TX1_D3N, AE15 MIPI_DSI_TX1_CLKN, AE18 MIPI_DSI_TX1_D0N, W15 MIPI_DSI_TX1_AVDD_0V9, Y15 MIPI_DSI_TX1_AVDD_1V8
part T pins: J28 eDP_TX_D0P, K27 eDP_TX_D0N, K28 eDP_TX_D1P, L25 eDP_TX_AUXP, L27 eDP_TX_D1N, L28 eDP_TX_D2P, M20 eDP_TX_AVDD_0V9, M22 eDP_TX_AVDD_1V8, M25 eDP_TX_AUXN, M27 eDP_TX_D2N, M28 eDP_TX_D3P, N27 eDP_TX_D3N
part U pins: L23 USB3_OTG0_ID, M23 USB3_AVDD_3V3, M24 USB3_OTG0_VBUSDET, P22 USB3_AVDD_0V9, P23 USB3_AVDD_1V8, P24 USB3_HOST1_DP, P25 USB3_HOST1_DM, P27 USB3_OTG0_DP, P28 USB3_OTG0_DM, R20 MULTI_PHY_AVDD_0V9_1, R21 MULTI_PHY_AVDD_0V9_2, R22 MULTI_PHY_AVDD_1V8, R24 MULTI_PHY0_REFCLKP, R25 MULTI_PHY0_REFCLKN, R27 USB3_OTG0_SSRXN/SATA0_RXN, R28 USB3_OTG0_SSRXP/SATA0_RXP, T27 USB3_OTG0_SSTXN/SATA0_TXN, T28 USB3_OTG0_SSTXP/SATA0_TXP, U24 MULTI_PHY1_REFCLKN, U25 MULTI_PHY1_REFCLKP, U27 USB3_HOST1_SSRXN/SATA1_RXN/QSGMII_RXN_M0, U28 USB3_HOST1_SSRXP/SATA1_RXP/QSGMII_RXP_M0, V24 PCIE20_REFCLKP, V25 PCIE20_REFCLKN, V27 USB3_HOST1_SSTXN/SATA1_TXN/QSGMII_TXN_M0, V28 USB3_HOST1_SSTXP/SATA1_TXP/QSGMII_TXP_M0, W27 PCIE20_TXP/SATA2_TXP/QSGMII_TXP_M1, W28 PCIE20_TXN/SATA2_TXN/QSGMII_TXN_M1, Y27 PCIE20_RXP/SATA2_RXP/QSGMII_RXP_M1, Y28 PCIE20_RXN/SATA2_RXN/QSGMII_RXN_M1
part V pins: P9 USB2_AVDD_1V8, P10 USB2_AVDD_3V3, R1 USB2_HOST2_DM, R2 USB2_HOST2_DP, R8 USB2_AVDD_0V9, T1 USB2_HOST3_DM, T2 USB2_HOST3_DP
part W pins: AA25 PCIE30_REFCLKN_IN, AA27 PCIE30_TX0N, AA28 PCIE30_TX0P, AB27 PCIE30_TX1N, AB28 PCIE30_TX1P, AC27 PCIE30_RX0N, AC28 PCIE30_RX0P, AD27 PCIE30_RX1N, AD28 PCIE30_RX1P, U19 PCIE30_RESREF, U20 PCIE30_AVDD_0V9_2, U21 PCIE30_AVDD_0V9_1, U22 PCIE30_AVDD_1V8, Y25 PCIE30_REFCLKP_IN

## RT8097CHGB
designator U?
pins: 1 EN, 2 GND (power), 3 LX (power), 4 VIN (power), 5 FB

## RT9193-GB
designator U?
CLASS: IC
pins: 1 IN (power), 2 GND (power), 3 ~{SHDN} (in), 4 BP (in), 5 OUT (power)

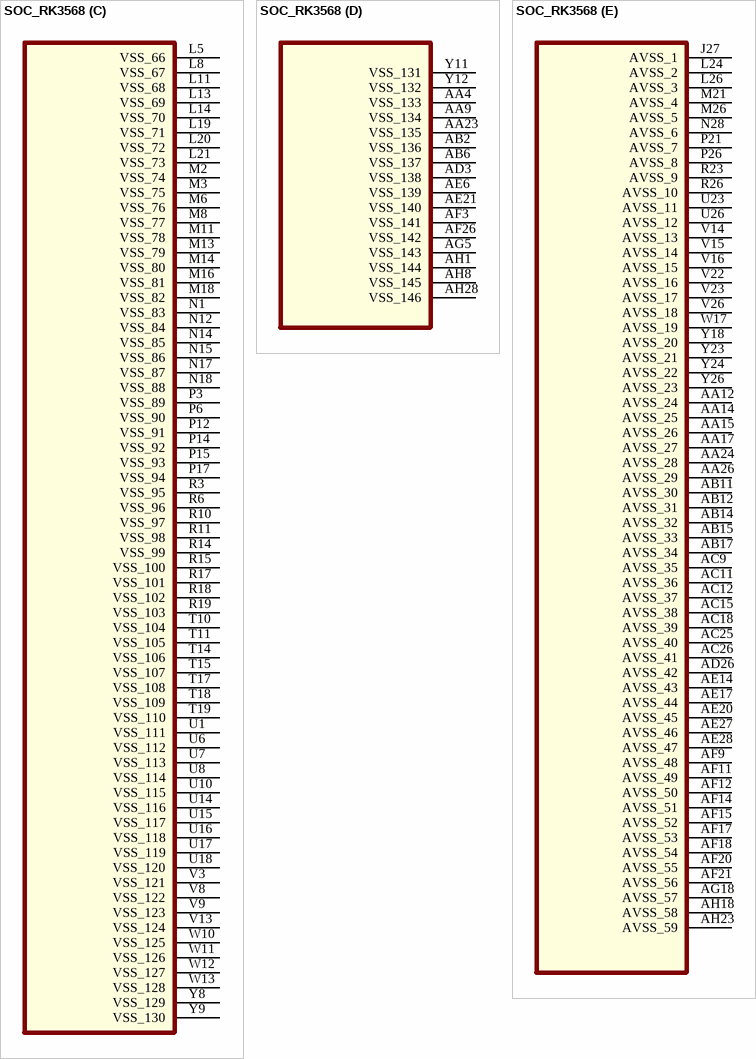
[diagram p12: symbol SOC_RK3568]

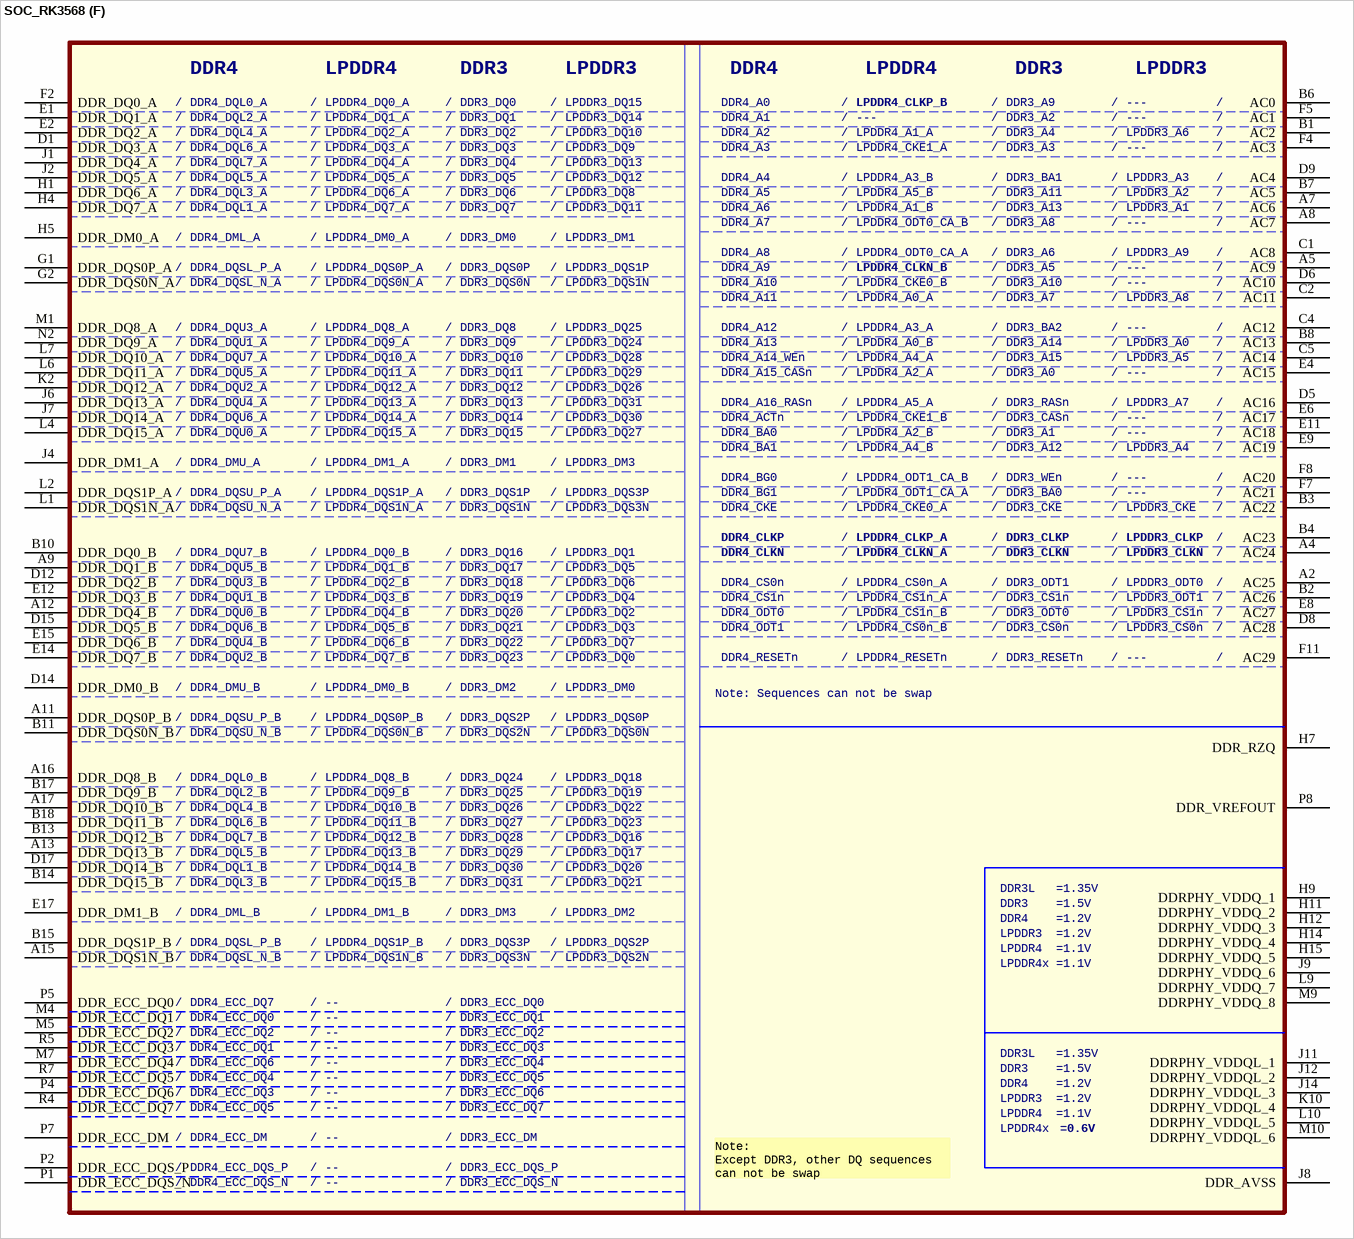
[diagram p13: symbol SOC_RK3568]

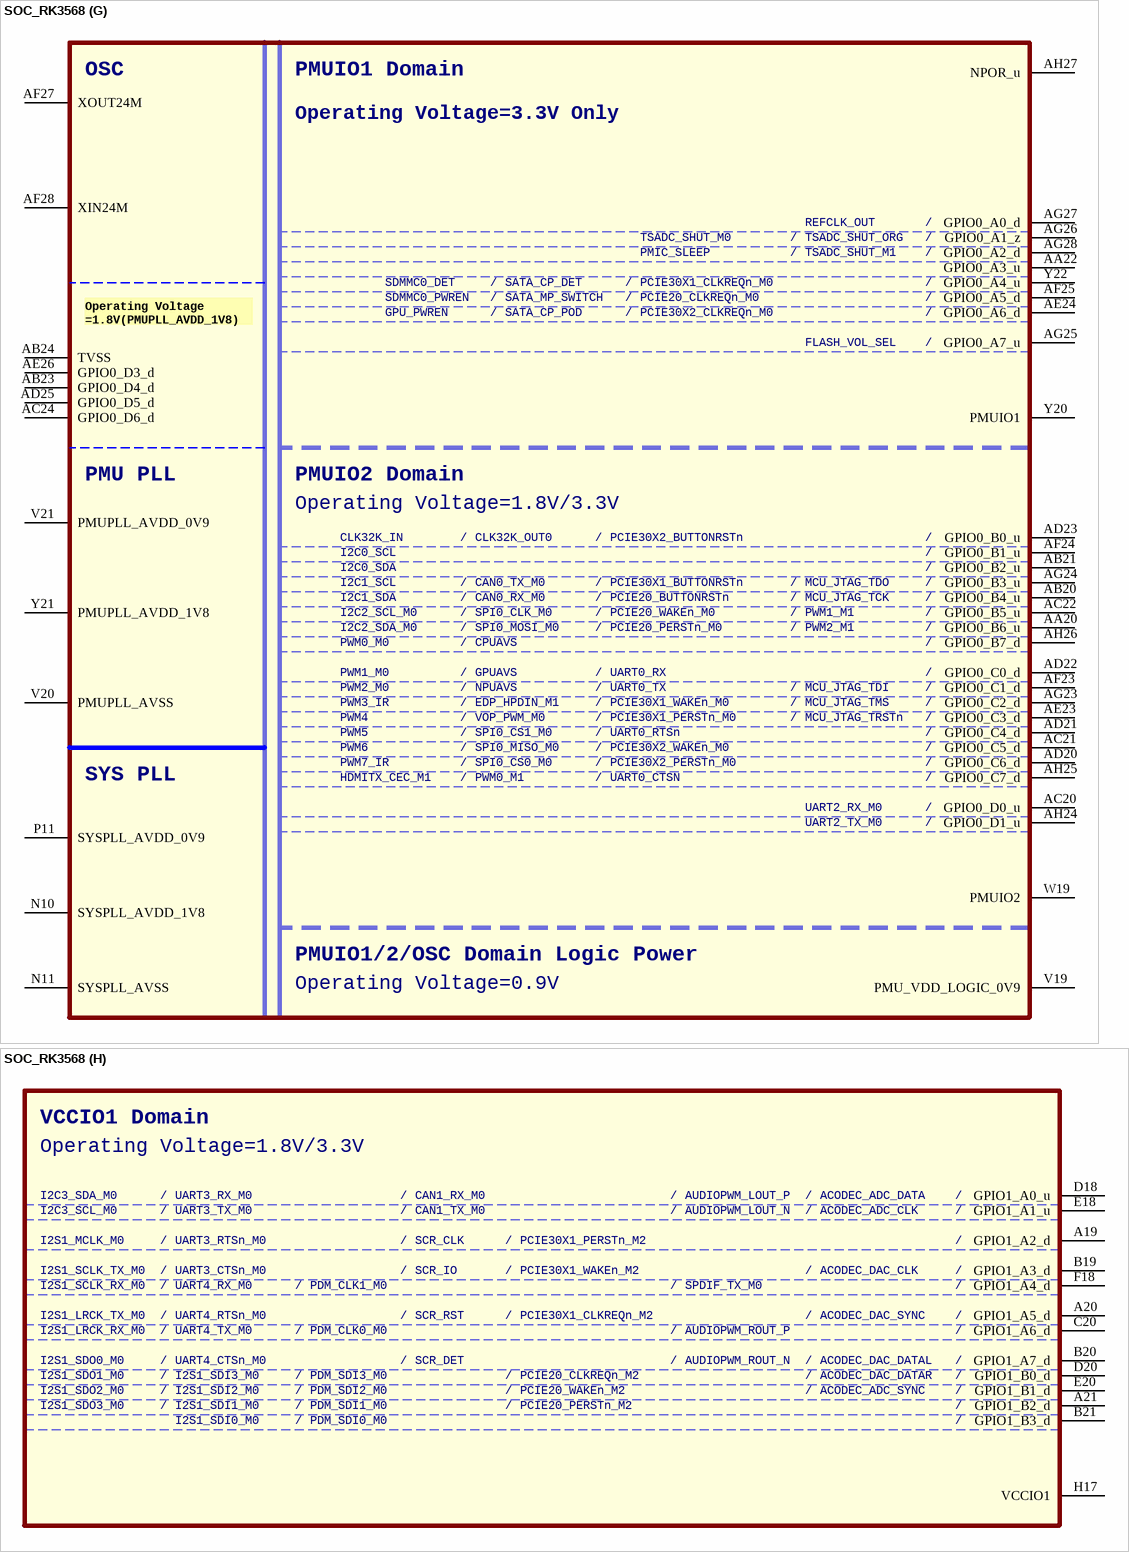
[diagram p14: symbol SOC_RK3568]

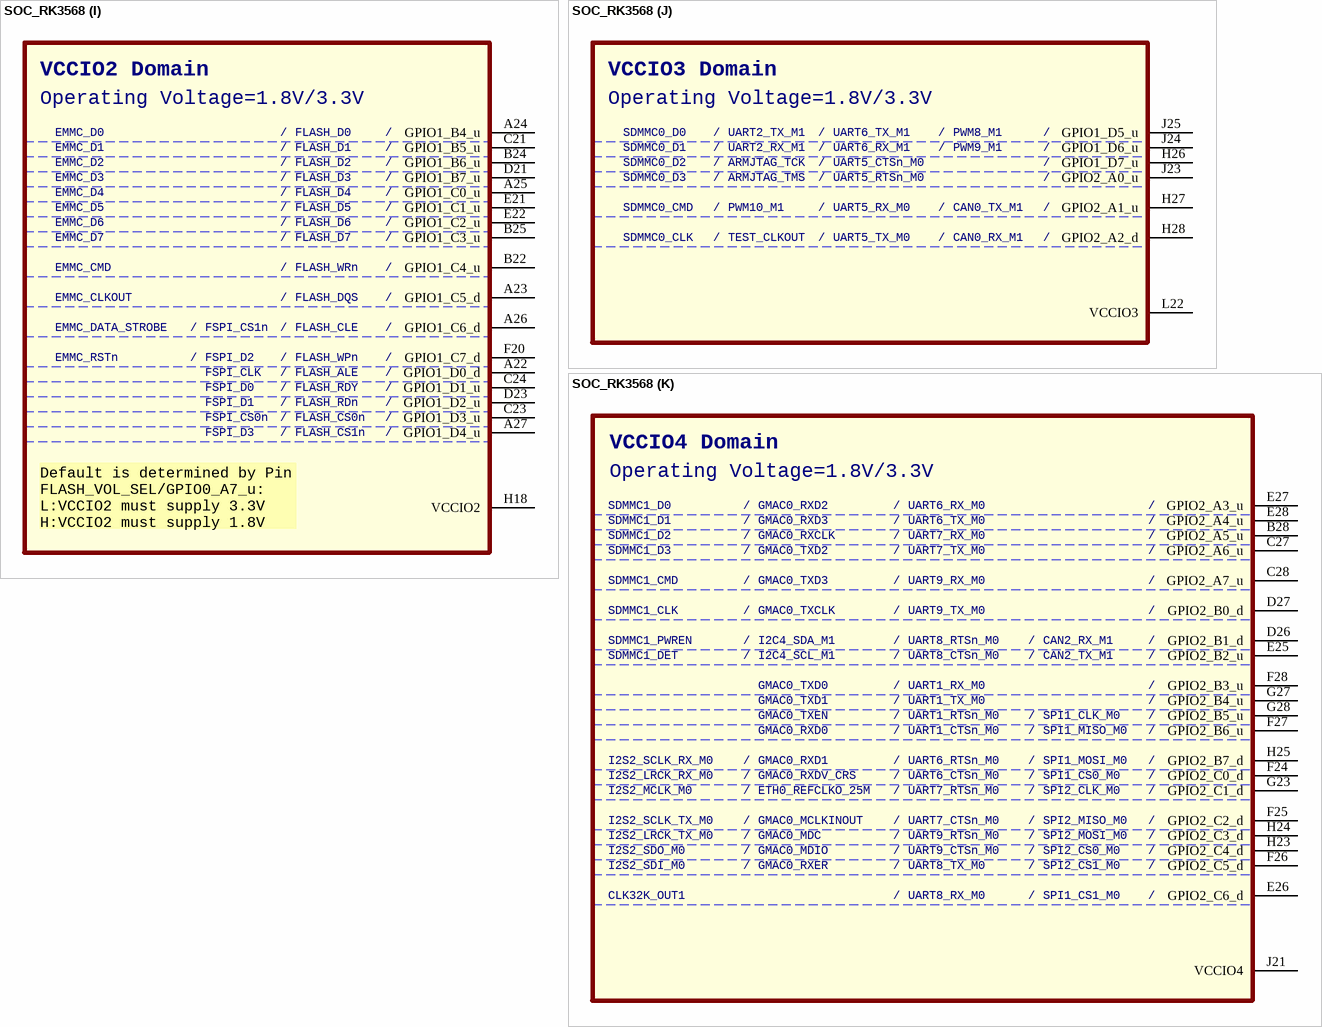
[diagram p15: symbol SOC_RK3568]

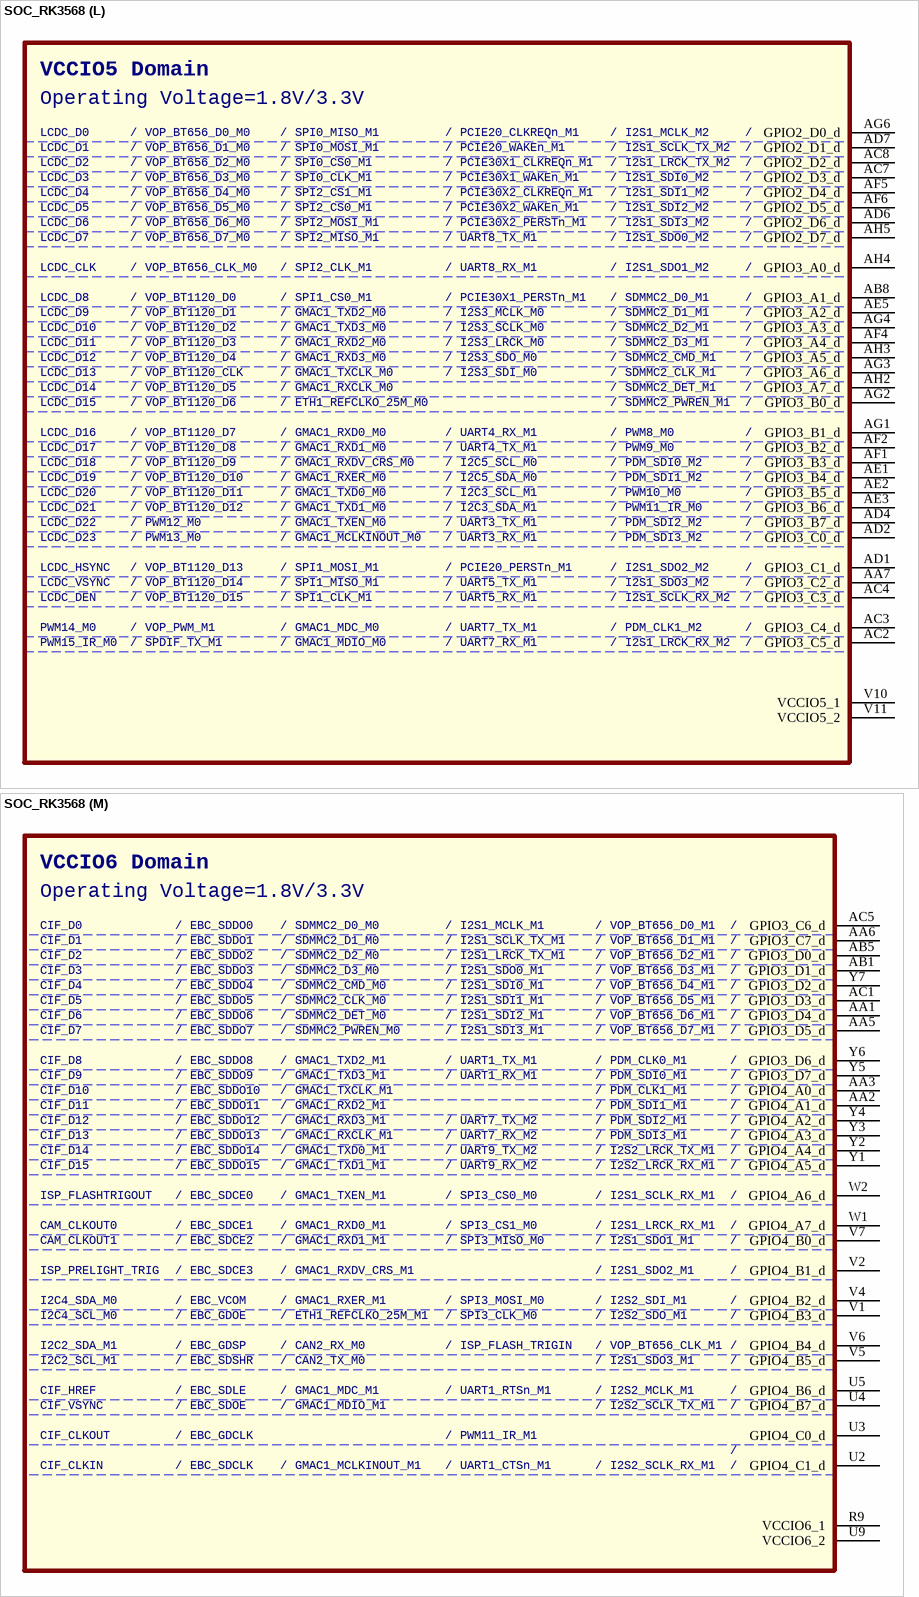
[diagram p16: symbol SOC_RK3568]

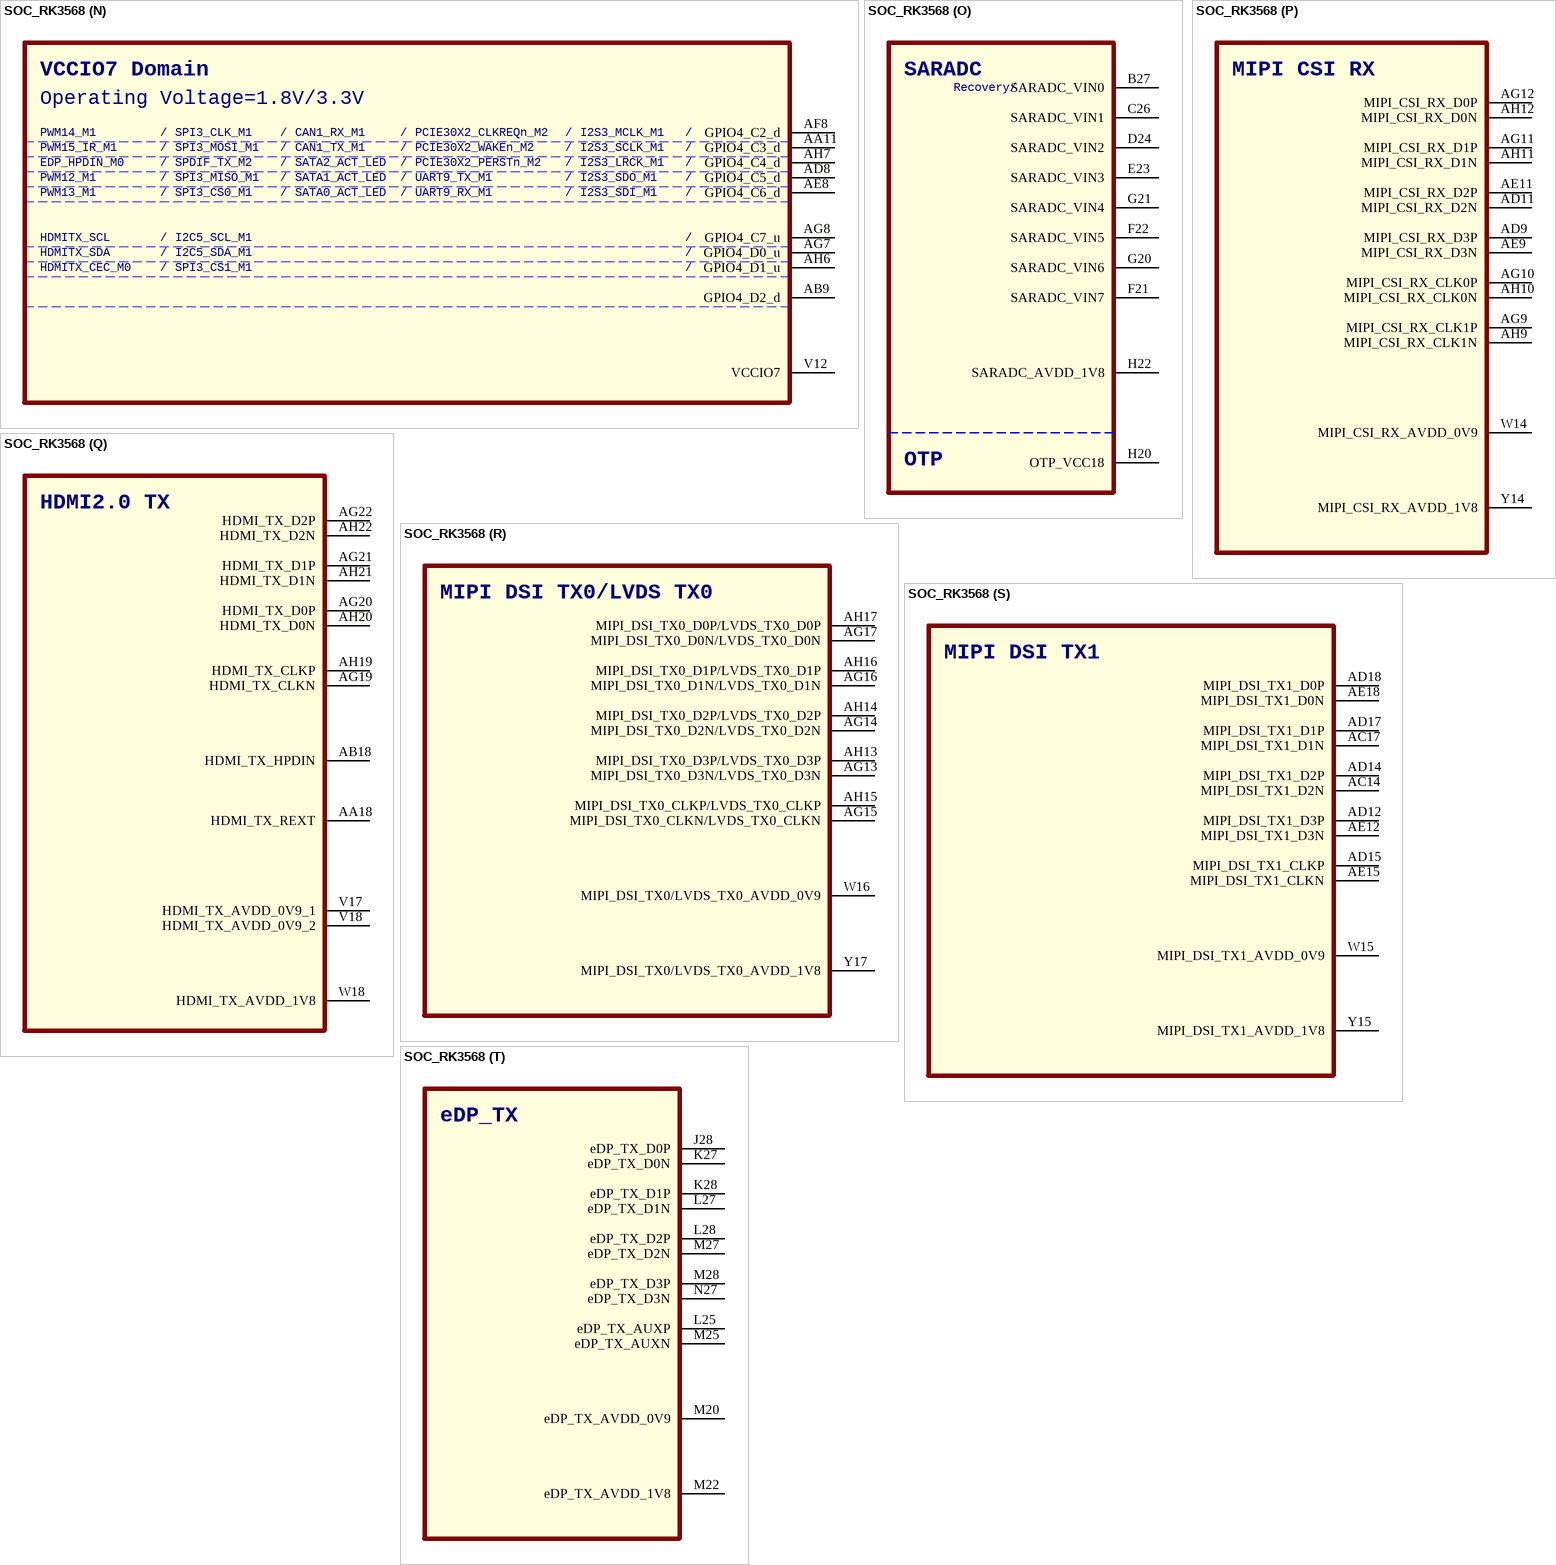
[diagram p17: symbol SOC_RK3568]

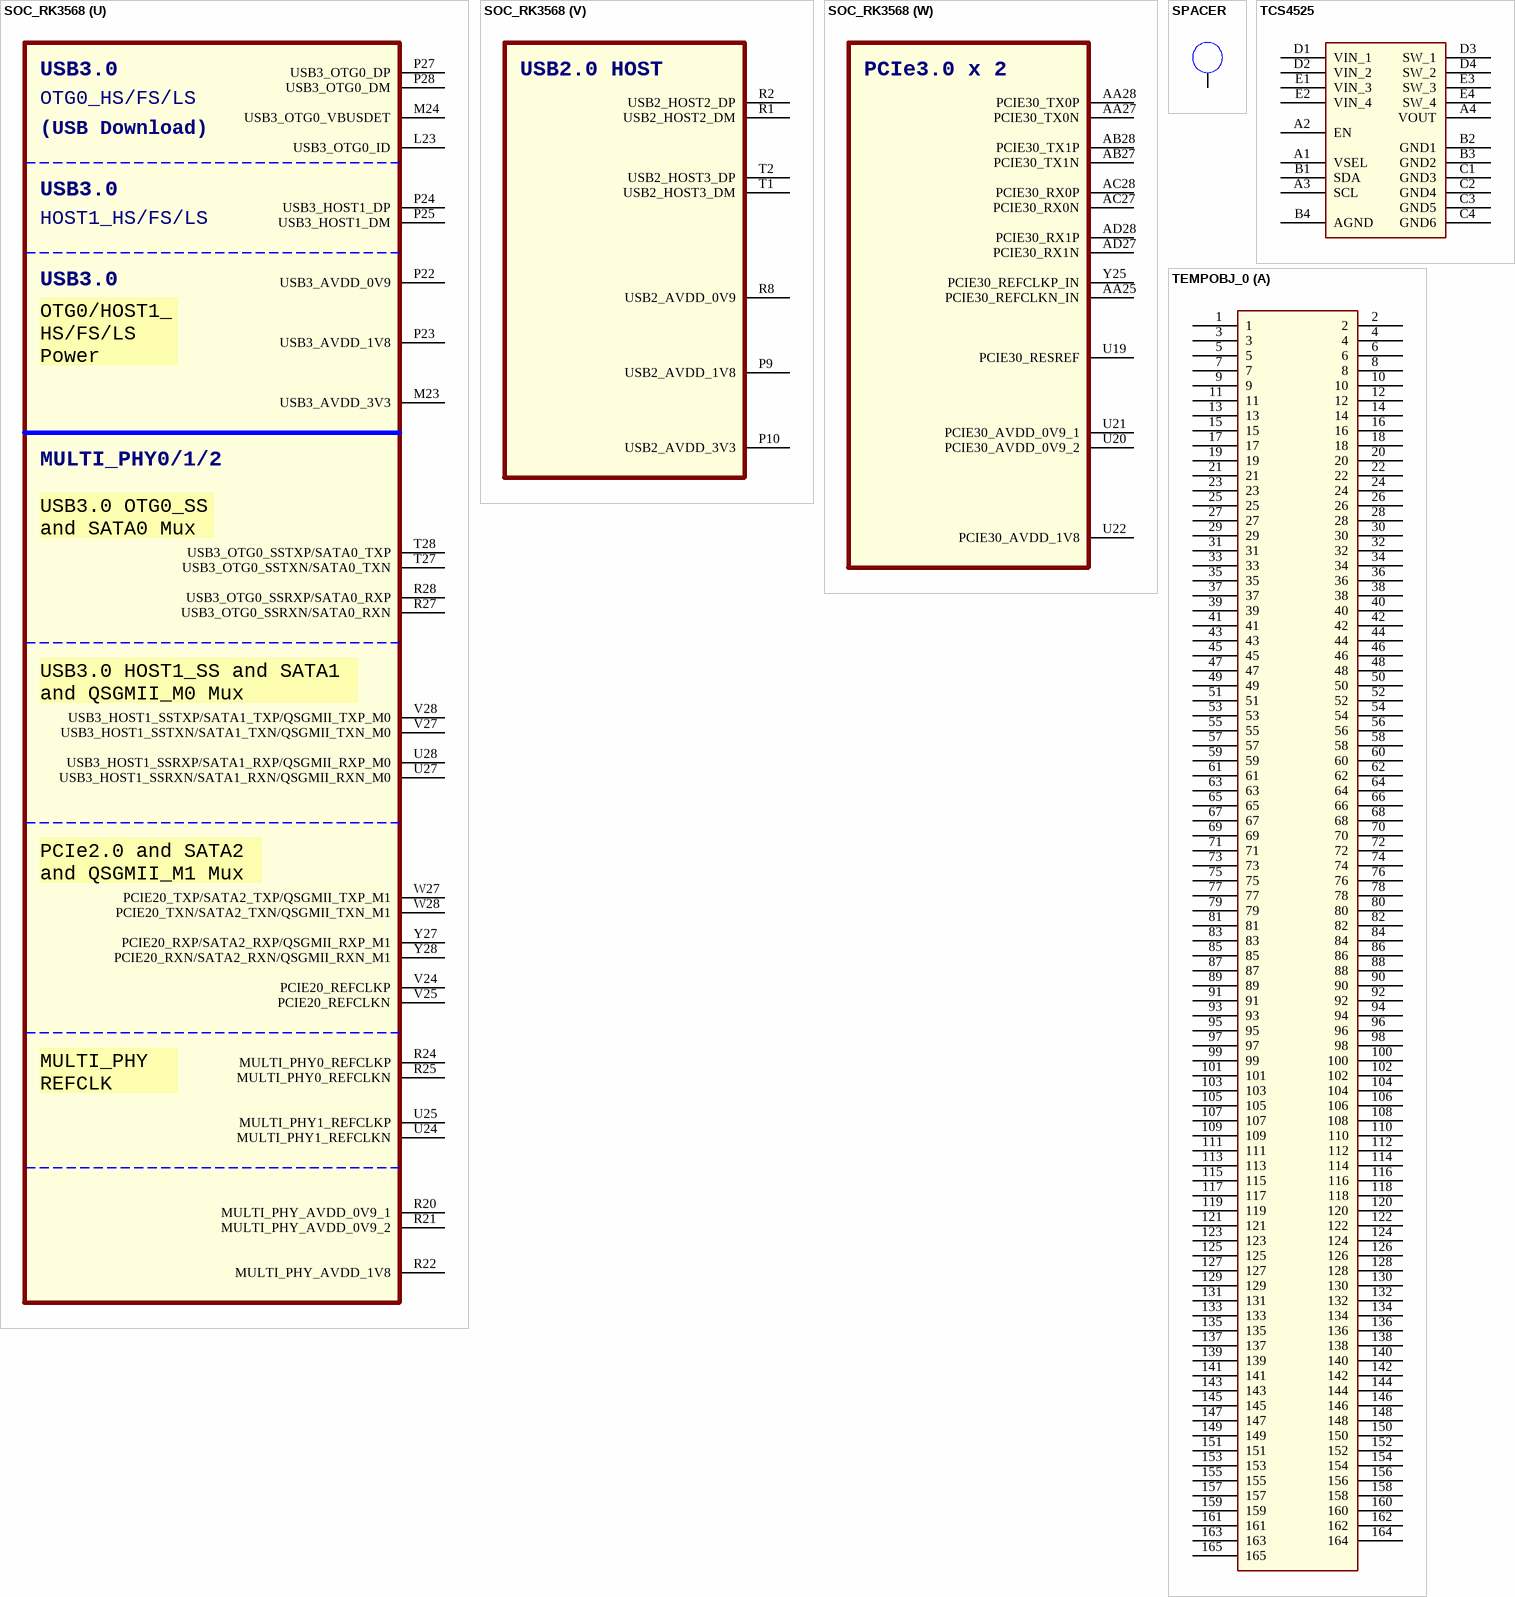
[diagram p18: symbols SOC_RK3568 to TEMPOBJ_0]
